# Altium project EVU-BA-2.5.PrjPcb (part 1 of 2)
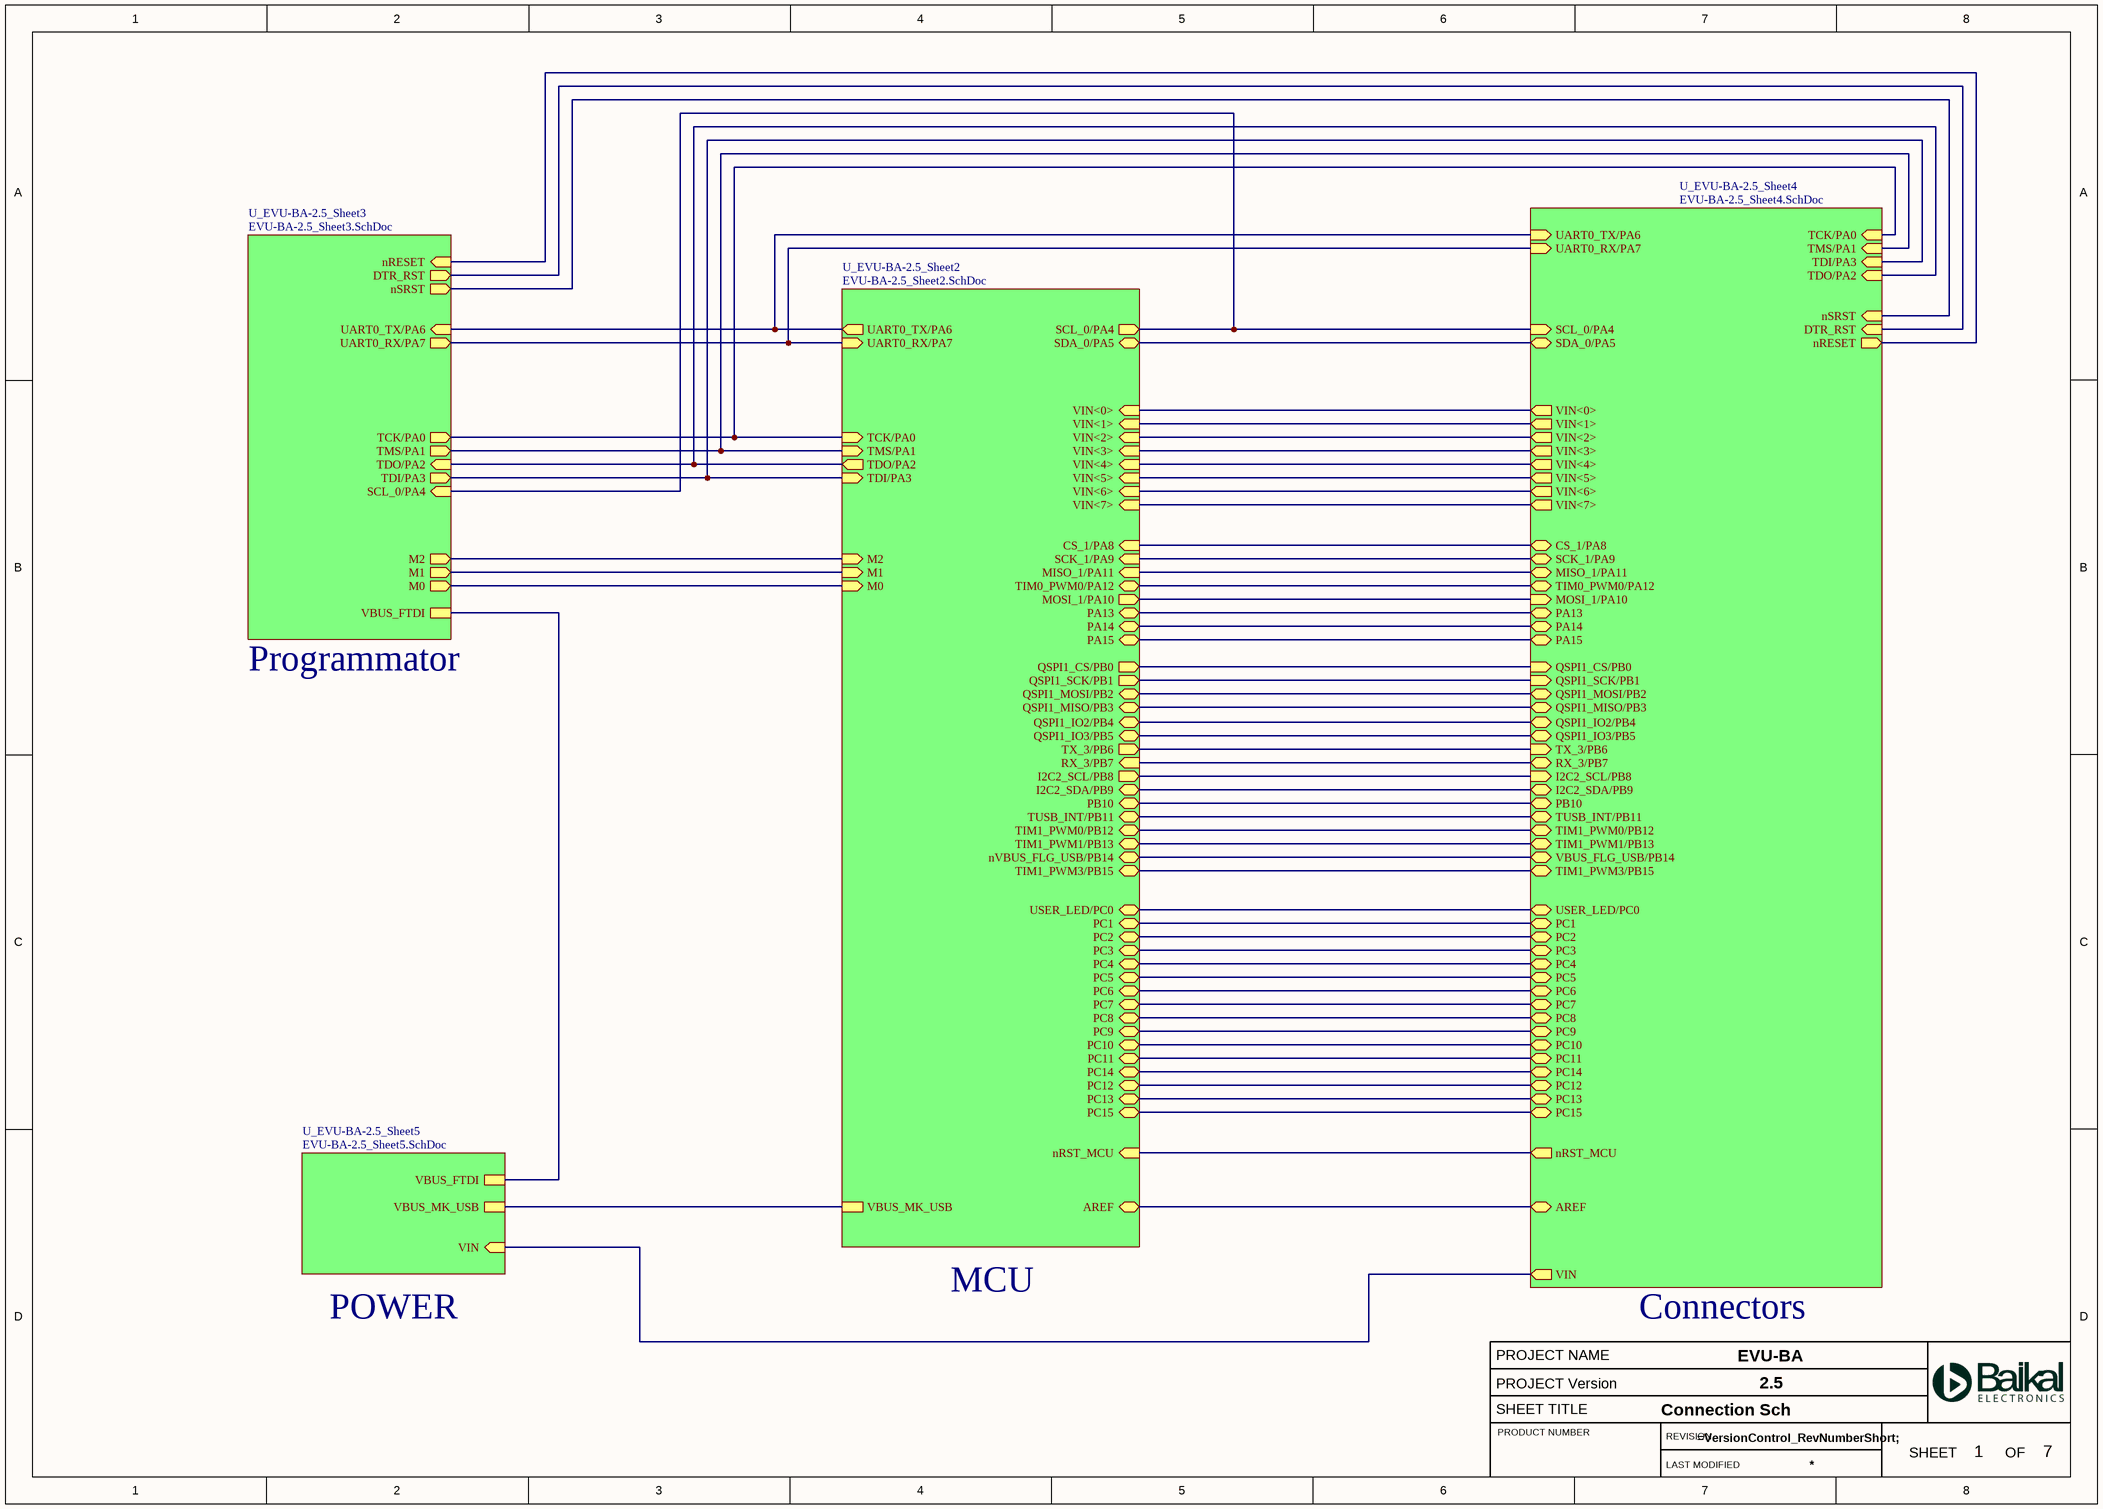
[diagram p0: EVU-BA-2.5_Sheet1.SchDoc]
Revision: =VersionControl_RevNumberShort; =CurrentTime
7 sheets, 254 parts. Net scope: hierarchical (ports join the sheet entries above them; power ports are global).
Board file: EVU-BA-2.5.PcbDoc
Sheets:
  EVU-BA-2.5_Sheet1.SchDoc
    U_EVU-BA-2.5_Sheet3 = EVU-BA-2.5_Sheet3.SchDoc
    U_EVU-BA-2.5_Sheet2 = EVU-BA-2.5_Sheet2.SchDoc
    U_EVU-BA-2.5_Sheet4 = EVU-BA-2.5_Sheet4.SchDoc
    U_EVU-BA-2.5_Sheet5 = EVU-BA-2.5_Sheet5.SchDoc
  EVU-BA-2.5_Sheet6.SchDoc
  EVU-BA-2.5_Sheet7.SchDoc

## Sheet EVU-BA-2.5_Sheet1.SchDoc: EVU-BA-2.5
size A3; ApprovedBy: Сподарец; CheckedBy: Цветков; Author: Гваськов; CompanyName: Baikal Electronics; SheetNumber: 1; SheetTotal: 7; Title2: Схема электрическая; Title3: принципиальная; PRJ: EVU-BA; Des: Baikal Electronics; VER: 2.5; TI: Connection Sch

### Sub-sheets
U_EVU-BA-2.5_Sheet2 = EVU-BA-2.5_Sheet2.SchDoc: VIN<0> (in), VIN<1> (in), VIN<2> (in), VIN<3> (in), VIN<4> (in), VIN<5> (in), VIN<6> (in), VIN<7> (in), USER_LED/PC0 (bidir), PC1 (bidir), PC2 (bidir), PC3 (bidir), PC4 (bidir), PC5 (bidir), PC6 (bidir), PC7 (bidir), PC8 (bidir), PC9 (bidir), PC10 (bidir), PC11 (bidir), PC14 (bidir), PC12 (bidir), PC13 (bidir), PC15 (bidir), TX_3/PB6 (out), RX_3/PB7 (in), TIM1_PWM0/PB12 (bidir), TIM1_PWM1/PB13 (bidir), TIM1_PWM3/PB15 (bidir), SDA_0/PA5 (bidir), TIM0_PWM0/PA12 (bidir), PA13 (bidir), PA14 (bidir), PA15 (bidir), VBUS_MK_USB, TUSB_INT/PB11 (bidir), I2C2_SDA/PB9 (bidir), PB10 (bidir), nVBUS_FLG_USB/PB14 (bidir), QSPI1_CS/PB0 (out), QSPI1_SCK/PB1 (out), QSPI1_MOSI/PB2 (bidir), QSPI1_MISO/PB3 (bidir), QSPI1_IO2/PB4 (bidir), QSPI1_IO3/PB5 (bidir), AREF (bidir), TCK/PA0 (in), TMS/PA1 (in), nRST_MCU (in), M2 (in), M1 (in), M0 (in), I2C2_SCL/PB8 (out), CS_1/PA8 (in), SCK_1/PA9 (in), MISO_1/PA11 (in), MOSI_1/PA10 (out), UART0_RX/PA7 (in), SCL_0/PA4 (out), UART0_TX/PA6 (out), TDO/PA2 (out), TDI/PA3 (in)
U_EVU-BA-2.5_Sheet3 = EVU-BA-2.5_Sheet3.SchDoc: VBUS_FTDI, SCL_0/PA4 (in), UART0_RX/PA7 (out), TCK/PA0 (out), TMS/PA1 (out), nRESET (in), nSRST (out), M2 (out), M1 (out), M0 (out), DTR_RST (out), TDI/PA3 (out), TDO/PA2 (in), UART0_TX/PA6 (in)
U_EVU-BA-2.5_Sheet4 = EVU-BA-2.5_Sheet4.SchDoc: VIN<0> (out), VIN<1> (out), VIN<2> (out), VIN<3> (out), VIN<4> (out), VIN<5> (out), VIN<6> (out), VIN<7> (out), SCL_0/PA4 (in), SDA_0/PA5 (bidir), CS_1/PA8 (bidir), SCK_1/PA9 (bidir), MISO_1/PA11 (bidir), TIM0_PWM0/PA12 (bidir), MOSI_1/PA10 (in), PA13 (bidir), PA14 (bidir), PA15 (bidir), TX_3/PB6 (in), RX_3/PB7 (bidir), TIM1_PWM0/PB12 (bidir), TIM1_PWM1/PB13 (bidir), TIM1_PWM3/PB15 (bidir), USER_LED/PC0 (bidir), PC1 (bidir), PC2 (bidir), PC3 (bidir), PC4 (bidir), PC5 (bidir), PC6 (bidir), PC7 (bidir), PC8 (bidir), PC9 (bidir), PC10 (bidir), PC11 (bidir), PC14 (bidir), PC12 (bidir), PC13 (bidir), PC15 (bidir), VIN (out), UART0_TX/PA6 (in), UART0_RX/PA7 (in), TUSB_INT/PB11 (bidir), I2C2_SCL/PB8 (in), I2C2_SDA/PB9 (bidir), PB10 (bidir), VBUS_FLG_USB/PB14 (bidir), QSPI1_CS/PB0 (in), QSPI1_SCK/PB1 (in), QSPI1_MOSI/PB2 (bidir), QSPI1_MISO/PB3 (bidir), QSPI1_IO2/PB4 (bidir), QSPI1_IO3/PB5 (bidir), AREF (bidir), TCK/PA0 (in), TMS/PA1 (in), TDI/PA3 (in), TDO/PA2 (in), nRST_MCU (out), nRESET (out), nSRST (in), DTR_RST (in)
U_EVU-BA-2.5_Sheet5 = EVU-BA-2.5_Sheet5.SchDoc: VBUS_FTDI, VIN (in), VBUS_MK_USB

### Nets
AREF: sheet U_EVU-BA-2.5_Sheet2/AREF, sheet U_EVU-BA-2.5_Sheet4/AREF
CS_1/PA8: sheet U_EVU-BA-2.5_Sheet2/CS_1/PA8, sheet U_EVU-BA-2.5_Sheet4/CS_1/PA8
DTR_RST: sheet U_EVU-BA-2.5_Sheet3/DTR_RST, sheet U_EVU-BA-2.5_Sheet4/DTR_RST
I2C2_SCL/PB8: sheet U_EVU-BA-2.5_Sheet2/I2C2_SCL/PB8, sheet U_EVU-BA-2.5_Sheet4/I2C2_SCL/PB8
I2C2_SDA/PB9: sheet U_EVU-BA-2.5_Sheet2/I2C2_SDA/PB9, sheet U_EVU-BA-2.5_Sheet4/I2C2_SDA/PB9
M0: sheet U_EVU-BA-2.5_Sheet3/M0, sheet U_EVU-BA-2.5_Sheet2/M0
M1: sheet U_EVU-BA-2.5_Sheet3/M1, sheet U_EVU-BA-2.5_Sheet2/M1
M2: sheet U_EVU-BA-2.5_Sheet3/M2, sheet U_EVU-BA-2.5_Sheet2/M2
MISO_1/PA11: sheet U_EVU-BA-2.5_Sheet2/MISO_1/PA11, sheet U_EVU-BA-2.5_Sheet4/MISO_1/PA11
MOSI_1/PA10: sheet U_EVU-BA-2.5_Sheet2/MOSI_1/PA10, sheet U_EVU-BA-2.5_Sheet4/MOSI_1/PA10
nRESET: sheet U_EVU-BA-2.5_Sheet3/nRESET, sheet U_EVU-BA-2.5_Sheet4/nRESET
nRST_MCU: sheet U_EVU-BA-2.5_Sheet2/nRST_MCU, sheet U_EVU-BA-2.5_Sheet4/nRST_MCU
nSRST: sheet U_EVU-BA-2.5_Sheet3/nSRST, sheet U_EVU-BA-2.5_Sheet4/nSRST
nVBUS_FLG_USB/PB14: sheet U_EVU-BA-2.5_Sheet2/nVBUS_FLG_USB/PB14, sheet U_EVU-BA-2.5_Sheet4/VBUS_FLG_USB/PB14
PA13: sheet U_EVU-BA-2.5_Sheet2/PA13, sheet U_EVU-BA-2.5_Sheet4/PA13
PA14: sheet U_EVU-BA-2.5_Sheet2/PA14, sheet U_EVU-BA-2.5_Sheet4/PA14
PA15: sheet U_EVU-BA-2.5_Sheet2/PA15, sheet U_EVU-BA-2.5_Sheet4/PA15
PB10: sheet U_EVU-BA-2.5_Sheet2/PB10, sheet U_EVU-BA-2.5_Sheet4/PB10
PC1: sheet U_EVU-BA-2.5_Sheet2/PC1, sheet U_EVU-BA-2.5_Sheet4/PC1
PC2: sheet U_EVU-BA-2.5_Sheet2/PC2, sheet U_EVU-BA-2.5_Sheet4/PC2
PC3: sheet U_EVU-BA-2.5_Sheet2/PC3, sheet U_EVU-BA-2.5_Sheet4/PC3
PC4: sheet U_EVU-BA-2.5_Sheet2/PC4, sheet U_EVU-BA-2.5_Sheet4/PC4
PC5: sheet U_EVU-BA-2.5_Sheet2/PC5, sheet U_EVU-BA-2.5_Sheet4/PC5
PC6: sheet U_EVU-BA-2.5_Sheet2/PC6, sheet U_EVU-BA-2.5_Sheet4/PC6
PC7: sheet U_EVU-BA-2.5_Sheet2/PC7, sheet U_EVU-BA-2.5_Sheet4/PC7
PC8: sheet U_EVU-BA-2.5_Sheet2/PC8, sheet U_EVU-BA-2.5_Sheet4/PC8
PC9: sheet U_EVU-BA-2.5_Sheet2/PC9, sheet U_EVU-BA-2.5_Sheet4/PC9
PC10: sheet U_EVU-BA-2.5_Sheet2/PC10, sheet U_EVU-BA-2.5_Sheet4/PC10
PC11: sheet U_EVU-BA-2.5_Sheet2/PC11, sheet U_EVU-BA-2.5_Sheet4/PC11
PC12: sheet U_EVU-BA-2.5_Sheet2/PC12, sheet U_EVU-BA-2.5_Sheet4/PC12
PC13: sheet U_EVU-BA-2.5_Sheet2/PC13, sheet U_EVU-BA-2.5_Sheet4/PC13
PC14: sheet U_EVU-BA-2.5_Sheet2/PC14, sheet U_EVU-BA-2.5_Sheet4/PC14
PC15: sheet U_EVU-BA-2.5_Sheet2/PC15, sheet U_EVU-BA-2.5_Sheet4/PC15
QSPI1_CS/PB0: sheet U_EVU-BA-2.5_Sheet2/QSPI1_CS/PB0, sheet U_EVU-BA-2.5_Sheet4/QSPI1_CS/PB0
QSPI1_IO2/PB4: sheet U_EVU-BA-2.5_Sheet2/QSPI1_IO2/PB4, sheet U_EVU-BA-2.5_Sheet4/QSPI1_IO2/PB4
QSPI1_IO3/PB5: sheet U_EVU-BA-2.5_Sheet2/QSPI1_IO3/PB5, sheet U_EVU-BA-2.5_Sheet4/QSPI1_IO3/PB5
QSPI1_MISO/PB3: sheet U_EVU-BA-2.5_Sheet2/QSPI1_MISO/PB3, sheet U_EVU-BA-2.5_Sheet4/QSPI1_MISO/PB3
QSPI1_MOSI/PB2: sheet U_EVU-BA-2.5_Sheet2/QSPI1_MOSI/PB2, sheet U_EVU-BA-2.5_Sheet4/QSPI1_MOSI/PB2
QSPI1_SCK/PB1: sheet U_EVU-BA-2.5_Sheet2/QSPI1_SCK/PB1, sheet U_EVU-BA-2.5_Sheet4/QSPI1_SCK/PB1
RX_3/PB7: sheet U_EVU-BA-2.5_Sheet2/RX_3/PB7, sheet U_EVU-BA-2.5_Sheet4/RX_3/PB7
SCK_1/PA9: sheet U_EVU-BA-2.5_Sheet2/SCK_1/PA9, sheet U_EVU-BA-2.5_Sheet4/SCK_1/PA9
SCL_0/PA4: sheet U_EVU-BA-2.5_Sheet3/SCL_0/PA4, sheet U_EVU-BA-2.5_Sheet2/SCL_0/PA4, sheet U_EVU-BA-2.5_Sheet4/SCL_0/PA4
SDA_0/PA5: sheet U_EVU-BA-2.5_Sheet2/SDA_0/PA5, sheet U_EVU-BA-2.5_Sheet4/SDA_0/PA5
TCK/PA0: sheet U_EVU-BA-2.5_Sheet3/TCK/PA0, sheet U_EVU-BA-2.5_Sheet2/TCK/PA0, sheet U_EVU-BA-2.5_Sheet4/TCK/PA0
TDI/PA3: sheet U_EVU-BA-2.5_Sheet3/TDI/PA3, sheet U_EVU-BA-2.5_Sheet2/TDI/PA3, sheet U_EVU-BA-2.5_Sheet4/TDI/PA3
TDO/PA2: sheet U_EVU-BA-2.5_Sheet3/TDO/PA2, sheet U_EVU-BA-2.5_Sheet2/TDO/PA2, sheet U_EVU-BA-2.5_Sheet4/TDO/PA2
TIM0_PWM0/PA12: sheet U_EVU-BA-2.5_Sheet2/TIM0_PWM0/PA12, sheet U_EVU-BA-2.5_Sheet4/TIM0_PWM0/PA12
TIM1_PWM0/PB12: sheet U_EVU-BA-2.5_Sheet2/TIM1_PWM0/PB12, sheet U_EVU-BA-2.5_Sheet4/TIM1_PWM0/PB12
TIM1_PWM1/PB13: sheet U_EVU-BA-2.5_Sheet2/TIM1_PWM1/PB13, sheet U_EVU-BA-2.5_Sheet4/TIM1_PWM1/PB13
TIM1_PWM3/PB15: sheet U_EVU-BA-2.5_Sheet2/TIM1_PWM3/PB15, sheet U_EVU-BA-2.5_Sheet4/TIM1_PWM3/PB15
TMS/PA1: sheet U_EVU-BA-2.5_Sheet3/TMS/PA1, sheet U_EVU-BA-2.5_Sheet2/TMS/PA1, sheet U_EVU-BA-2.5_Sheet4/TMS/PA1
TUSB_INT/PB11: sheet U_EVU-BA-2.5_Sheet2/TUSB_INT/PB11, sheet U_EVU-BA-2.5_Sheet4/TUSB_INT/PB11
TX_3/PB6: sheet U_EVU-BA-2.5_Sheet2/TX_3/PB6, sheet U_EVU-BA-2.5_Sheet4/TX_3/PB6
UART0_RX/PA7: sheet U_EVU-BA-2.5_Sheet3/UART0_RX/PA7, sheet U_EVU-BA-2.5_Sheet2/UART0_RX/PA7, sheet U_EVU-BA-2.5_Sheet4/UART0_RX/PA7
UART0_TX/PA6: sheet U_EVU-BA-2.5_Sheet3/UART0_TX/PA6, sheet U_EVU-BA-2.5_Sheet2/UART0_TX/PA6, sheet U_EVU-BA-2.5_Sheet4/UART0_TX/PA6
USER_LED/PC0: sheet U_EVU-BA-2.5_Sheet2/USER_LED/PC0, sheet U_EVU-BA-2.5_Sheet4/USER_LED/PC0
VBUS_FTDI: sheet U_EVU-BA-2.5_Sheet3/VBUS_FTDI, sheet U_EVU-BA-2.5_Sheet5/VBUS_FTDI
VBUS_MK_USB: sheet U_EVU-BA-2.5_Sheet2/VBUS_MK_USB, sheet U_EVU-BA-2.5_Sheet5/VBUS_MK_USB
VIN: sheet U_EVU-BA-2.5_Sheet4/VIN, sheet U_EVU-BA-2.5_Sheet5/VIN
VIN<0>: sheet U_EVU-BA-2.5_Sheet2/VIN<0>, sheet U_EVU-BA-2.5_Sheet4/VIN<0>
VIN<1>: sheet U_EVU-BA-2.5_Sheet2/VIN<1>, sheet U_EVU-BA-2.5_Sheet4/VIN<1>
VIN<2>: sheet U_EVU-BA-2.5_Sheet2/VIN<2>, sheet U_EVU-BA-2.5_Sheet4/VIN<2>
VIN<3>: sheet U_EVU-BA-2.5_Sheet2/VIN<3>, sheet U_EVU-BA-2.5_Sheet4/VIN<3>
VIN<4>: sheet U_EVU-BA-2.5_Sheet2/VIN<4>, sheet U_EVU-BA-2.5_Sheet4/VIN<4>
VIN<5>: sheet U_EVU-BA-2.5_Sheet2/VIN<5>, sheet U_EVU-BA-2.5_Sheet4/VIN<5>
VIN<6>: sheet U_EVU-BA-2.5_Sheet2/VIN<6>, sheet U_EVU-BA-2.5_Sheet4/VIN<6>
VIN<7>: sheet U_EVU-BA-2.5_Sheet2/VIN<7>, sheet U_EVU-BA-2.5_Sheet4/VIN<7>

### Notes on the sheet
- Programmator
- POWER
- MCU
- Connectors

## Sheet EVU-BA-2.5_Sheet3.SchDoc: EVU-BA-2.5
size A3; SheetNumber: 3; SheetTotal: 7; Prj: EVU-BA; Ti: USB UART Bridge; Ver: 2.5
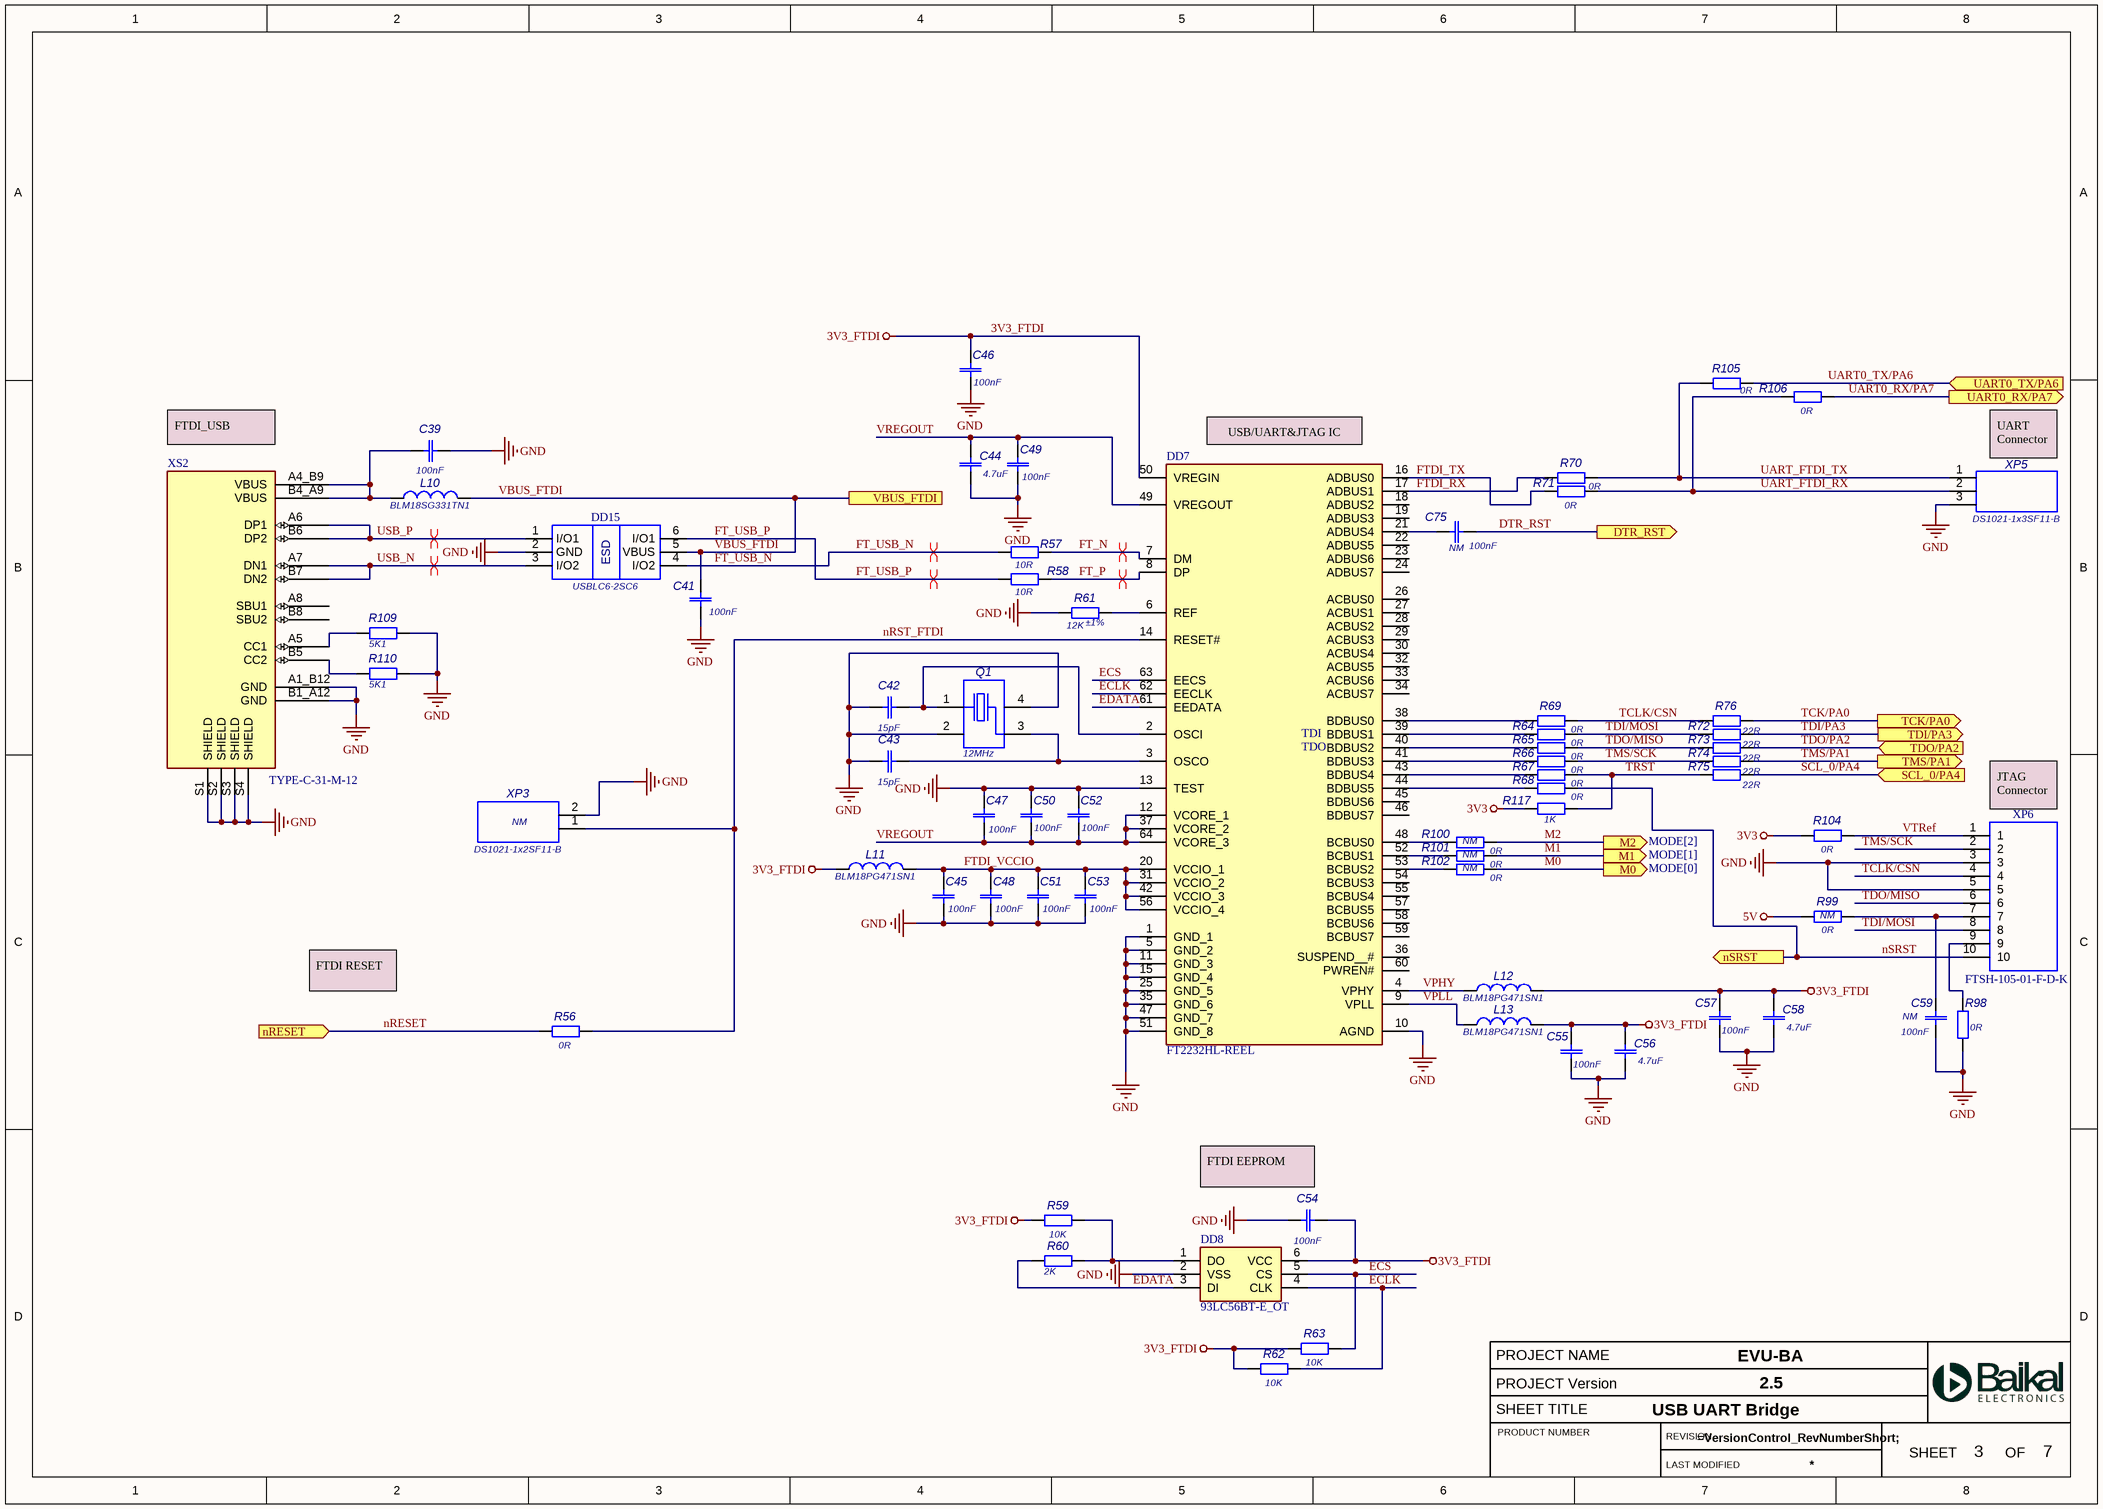
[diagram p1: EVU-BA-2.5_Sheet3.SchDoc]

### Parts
C39  value 100nF  [CAPC1608X80N]  (hidden comment: C0603C104K5RAC)
C41  value 100nF  [CAPC1608X80N]  (hidden comment: C0603C104K5RAC)
C42  value 15pF  [CAPC1005X50N]  (hidden comment: GRM1555C1H150JA01D)
C43  value 15pF  [CAPC1005X50N]  (hidden comment: GRM1555C1H150JA01D)
C44  value 4.7uF  [CAPC1608X80N]  (hidden comment: GRM188R60J475KE19D)
C45  value 100nF  [CAPC1608X80N]  (hidden comment: C0603C104K5RAC)
C46  value 100nF  [CAPC1608X80N]  (hidden comment: C0603C104K5RAC)
C47  value 100nF  [CAPC1608X80N]  (hidden comment: C0603C104K5RAC)
C48  value 100nF  [CAPC1608X80N]  (hidden comment: C0603C104K5RAC)
C49  value 100nF  [CAPC1608X80N]  (hidden comment: C0603C104K5RAC)
C50  value 100nF  [CAPC1608X80N]  (hidden comment: C0603C104K5RAC)
C51  value 100nF  [CAPC1608X80N]  (hidden comment: C0603C104K5RAC)
C52  value 100nF  [CAPC1608X80N]  (hidden comment: C0603C104K5RAC)
C53  value 100nF  [CAPC1608X80N]  (hidden comment: C0603C104K5RAC)
C54  value 100nF  [CAPC1608X80N]  (hidden comment: C0603C104K5RAC)
C55  value 100nF  [CAPC1608X80N]  (hidden comment: C0603C104K5RAC)
C56  value 4.7uF  [CAPC1608X80N]  (hidden comment: GRM188R60J475KE19D)
C57  value 100nF  [CAPC1608X80N]  (hidden comment: C0603C104K5RAC)
C58  value 4.7uF  [CAPC1608X80N]  (hidden comment: GRM188R60J475KE19D)
C59  value 100nF  DNP: NM  [CAPC1608X80N]  (hidden comment: C0603C104K5RAC)
C75  value 100nF  DNP: NM  [CAPC1608X80N]  (hidden comment: C0603C104K5RAC)
DD7  FT2232HL-REEL  [QFP50P1200X1200X160-64N]
DD8  93LC56BT-E_OT  [SOT95P280X145-6N]
DD15  USBLC6-2SC6  [SOT95P280X145-6N]
L10  BLM18SG331TN1  [INDC1608X95N]
L11  BLM18PG471SN1  [BLM18X16X08X60N]
L12  BLM18PG471SN1  [BLM18X16X08X60N]
L13  BLM18PG471SN1  [BLM18X16X08X60N]
Q1  value 12MHz  [JXS32X330X270X70N]  (hidden comment: X322512MSB4SI)
R56  value 0R  [RESC1608X45N]  (hidden comment: CR0603-J/-000-E)
R57  value 10R  [RESC1608X45N]  (hidden comment: CR0603-JW-100-E)
R58  value 10R  [RESC1608X45N]  (hidden comment: CR0603-JW-100-E)
R59  value 10K  [RESC1608X45N]  (hidden comment: CR0603-JW-103-E)
R60  value 2K  [RESC1608X45N]  (hidden comment: CR0603-JW-202-E)
R61  value 12K  Tolerance: ±1%  [RESC1608X45N]  (hidden comment: CR0603-FX-1202-E)
R62  value 10K  [RESC1608X45N]  (hidden comment: CR0603-JW-103-E)
R63  value 10K  [RESC1608X45N]  (hidden comment: CR0603-JW-103-E)
R64  value 0R  [RESC1608X45N]  (hidden comment: CR0603-J/-000-E)
R65  value 0R  [RESC1608X45N]  (hidden comment: CR0603-J/-000-E)
R66  value 0R  [RESC1608X45N]  (hidden comment: CR0603-J/-000-E)
R67  value 0R  [RESC1608X45N]  (hidden comment: CR0603-J/-000-E)
R68  value 0R  [RESC1608X45N]  (hidden comment: CR0603-J/-000-E)
R69  value 0R  [RESC1608X45N]  (hidden comment: CR0603-J/-000-E)
R70  value 0R  [RESC1608X45N]  (hidden comment: CR0603-J/-000-E)
R71  value 0R  [RESC1608X45N]  (hidden comment: CR0603-J/-000-E)
R72  value 22R  [RESC1608X45N]  (hidden comment: CR0603-JW-220-E)
R73  value 22R  [RESC1608X45N]  (hidden comment: CR0603-JW-220-E)
R74  value 22R  [RESC1608X45N]  (hidden comment: CR0603-JW-220-E)
R75  value 22R  [RESC1608X45N]  (hidden comment: CR0603-JW-220-E)
R76  value 22R  [RESC1608X45N]  (hidden comment: CR0603-JW-220-E)
R98  value 0R  [RESC1608X45N]  (hidden comment: CR0603-J/-000-E)
R99  value 0R  DNP: NM  [RESC1608X45N]  (hidden comment: CR0603-J/-000-E)
R100  value 0R  DNP: NM  [RESC1608X45N]  (hidden comment: CR0603-J/-000-E)
R101  value 0R  DNP: NM  [RESC1608X45N]  (hidden comment: CR0603-J/-000-E)
R102  value 0R  DNP: NM  [RESC1608X45N]  (hidden comment: CR0603-J/-000-E)
R104  value 0R  [RESC1608X45N]  (hidden comment: CR0603-J/-000-E)
R105  value 0R  [RESC1608X45N]  (hidden comment: CR0603-J/-000-E)
R106  value 0R  [RESC1608X45N]  (hidden comment: CR0603-J/-000-E)
R109  Value Eng: 5K1  [RESC1608X45N]  (hidden comment: CR0603-JW-512-E)
R110  Value Eng: 5K1  [RESC1608X45N]  (hidden comment: CR0603-JW-512-E)
R117  Value Eng: 1K  [RESC1608X45N]  (hidden comment: CR0603-JW-102-E)
XP3  DS1021-1x2SF11-B  DNP: NM  [PLS2-254PX50X25X854N]
XP5  DS1021-1x3SF11-B  [PLS3-254PX76X25X854N]
XP6  FTSH-105-01-F-D-K  [FTSH-105-XX-YYY-D-K]
XS2  TYPE-C-31-M-12  [TYPE-C-31-M-12]

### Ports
DTR_RST (out, see EVU-BA-2.5_Sheet1[7D], EVU-BA-2.5_Sheet4[6A]), M0 (out, see EVU-BA-2.5_Sheet1[7C], EVU-BA-2.5_Sheet2[8D]), M1 (out, see EVU-BA-2.5_Sheet1[7C], EVU-BA-2.5_Sheet2[8D]), M2 (out, see EVU-BA-2.5_Sheet1[7C], EVU-BA-2.5_Sheet2[8D]), nRESET (in, see EVU-BA-2.5_Sheet1[7D], EVU-BA-2.5_Sheet4[7A]), nSRST (out, see EVU-BA-2.5_Sheet1[7D], EVU-BA-2.5_Sheet4[7A]), SCL_0/PA4 (in, see EVU-BA-2.5_Sheet1[7C], EVU-BA-2.5_Sheet2[5D], EVU-BA-2.5_Sheet4[8D]), TCK/PA0 (out, see EVU-BA-2.5_Sheet1[7C], EVU-BA-2.5_Sheet2[5D], EVU-BA-2.5_Sheet4[8D]), TDI/PA3 (out, see EVU-BA-2.5_Sheet1[7C], EVU-BA-2.5_Sheet2[5D], EVU-BA-2.5_Sheet4[8D]), TDO/PA2 (in, see EVU-BA-2.5_Sheet1[7C], EVU-BA-2.5_Sheet2[5D], EVU-BA-2.5_Sheet4[8D]), TMS/PA1 (out, see EVU-BA-2.5_Sheet1[7C], EVU-BA-2.5_Sheet2[5D], EVU-BA-2.5_Sheet4[8D]), UART0_RX/PA7 (out, see EVU-BA-2.5_Sheet1[7D], EVU-BA-2.5_Sheet2[5D], EVU-BA-2.5_Sheet4[8D]), UART0_TX/PA6 (in, see EVU-BA-2.5_Sheet1[7D], EVU-BA-2.5_Sheet2[5D], EVU-BA-2.5_Sheet4[8D]), VBUS_FTDI (see EVU-BA-2.5_Sheet1[7C], EVU-BA-2.5_Sheet5[8D])

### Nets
3V3: R104.1 R117.1
3V3_FTDI: C46.2 C54.1 C55.2 C56.2 C57.2 C58.2 DD7.50(VREGIN) DD8.6(VCC) L11.1 L12.2 L13.2 R59.1 R62.1 R63.1
5V: R99.2
GND: C39.2 C41.2 C42.1 C43.1 C44.1 C45.1 C46.1 C47.2 C48.1 C49.1 C50.2 C51.1 C52.2 C53.1 C54.2 C55.1 C56.1 C57.1 C58.1 C59.1 DD7.1(GND_1) DD7.5(GND_2) DD7.10(AGND) DD7.11(GND_3) DD7.13(TEST) DD7.15(GND_4) DD7.25(GND_5) DD7.35(GND_6) DD7.47(GND_7) DD7.51(GND_8) DD8.2(VSS) DD15.2(GND) Q1.2 Q1.4 R61.1 R98.2 R109.2 R110.2 XP3.2 XP5.3 XP6.3 XP6.5 XS2.A1_B12(GND) XS2.B1_A12(GND) XS2.S1(SHIELD) XS2.S2(SHIELD) XS2.S3(SHIELD) XS2.S4(SHIELD)
DTR_RST: C75.1 ; port DTR_RST
ECLK: DD7.62(EECLK) DD8.4(CLK) R62.2
ECS: DD7.63(EECS) DD8.5(CS) R63.2
EDATA: DD7.61(EEDATA) DD8.3(DI) R60.1
FT_N: DD7.7(DM) R57.2
FT_P: DD7.8(DP) R58.2
FT_USB_N: DD15.4(I/O2) R57.1
FT_USB_P: DD15.6(I/O1) R58.1
FTDI_RX: DD7.17(ADBUS1) R70.1
FTDI_TX: DD7.16(ADBUS0) R71.1
FTDI_VCCIO: C45.2 C48.2 C51.2 C53.2 DD7.20(VCCIO_1) DD7.31(VCCIO_2) DD7.42(VCCIO_3) DD7.56(VCCIO_4) L11.2
M0: R102.2 ; port M0
M1: R101.2 ; port M1
M2: R100.2 ; port M2
nRESET: R56.1 ; port nRESET
nRST_FTDI: DD7.14(RESET#) R56.2 XP3.1
nSRST: R68.2 XP6.10 ; port nSRST
SCL_0/PA4: R75.2 ; port SCL_0/PA4
TCK/PA0: R76.2 ; port TCK/PA0
TCLK/CSN: R69.2 R76.1 XP6.4
TDI/MOSI: R64.2 R72.1 XP6.8
TDI/PA3: R72.2 ; port TDI/PA3
TDO/MISO: R65.2 R73.1 XP6.6
TDO/PA2: R73.2 ; port TDO/PA2
TMS/PA1: R74.2 ; port TMS/PA1
TMS/SCK: R66.2 R74.1 XP6.2
TRST: R67.2 R75.1 R117.2
UART0_RX/PA7: R106.2 ; port UART0_RX/PA7
UART0_TX/PA6: R105.2 ; port UART0_TX/PA6
UART_FTDI_RX: R71.2 R106.1 XP5.2
UART_FTDI_TX: R70.2 R105.1 XP5.1
USB_N: DD15.3(I/O2) XS2.A7(DN1) XS2.B7(DN2)
USB_P: DD15.1(I/O1) XS2.A6(DP1) XS2.B6(DP2)
VBUS_FTDI: C41.1 DD15.5(VBUS) L10.2 ; port VBUS_FTDI
VPHY: DD7.4(VPHY) L12.1
VPLL: DD7.9(VPLL) L13.1
VREGOUT: C44.2 C47.1 C49.2 C50.1 C52.1 DD7.12(VCORE_1) DD7.37(VCORE_2) DD7.49(VREGOUT) DD7.64(VCORE_3)
VTRef: R104.2 XP6.1
NetC39_1: C39.1 L10.1 XS2.A4_B9(VBUS) XS2.B4_A9(VBUS)
NetC42_2: C42.2 DD7.2(OSCI) Q1.1
NetC43_2: C43.2 DD7.3(OSCO) Q1.3
NetC59_2: C59.2 R99.1 XP6.7
NetC75_2: C75.2 DD7.21(ADBUS4)
NetDD7_6: DD7.6(REF) R61.2
NetDD7_38: DD7.38(BDBUS0) R69.1
NetDD7_39: DD7.39(BDBUS1) R64.1
NetDD7_40: DD7.40(BDBUS2) R65.1
NetDD7_41: DD7.41(BDBUS3) R66.1
NetDD7_43: DD7.43(BDBUS4) R67.1
NetDD7_44: DD7.44(BDBUS5) R68.1
NetDD7_48: DD7.48(BCBUS0) R100.1
NetDD7_52: DD7.52(BCBUS1) R101.1
NetDD7_53: DD7.53(BCBUS2) R102.1
NetDD8_1: DD8.1(DO) R59.2 R60.2
NetR98_1: R98.1 XP6.9
NetR109_1: R109.1 XS2.A5(CC1)
NetR110_1: R110.1 XS2.B5(CC2)

Not connected (* = marked no-connect by the designer): DD7 18(ADBUS2) 19(ADBUS3) 22(ADBUS5) 23(ADBUS6) 24(ADBUS7) 26(ACBUS0) 27(ACBUS1) 28(ACBUS2) 29(ACBUS3) 30(ACBUS4) 32(ACBUS5) 33(ACBUS6) 34(ACBUS7) 36(SUSPEND__#) 45(BDBUS6) 46(BDBUS7) 54(BCBUS3) 55(BCBUS4) 57(BCBUS5) 58(BCBUS6) 59(BCBUS7) 60(PWREN#); XS2 A8(SBU1) B8(SBU2)

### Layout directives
differential pair: FT_N, FT_P, FT_USB_N, FT_USB_P, USB_N, USB_P

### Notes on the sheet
- (near XS2) FTDI_USB
- (near DD7) USB/UART&JTAG IC
- (near XP5) UART Connector
- (near DD7) TDI
- (near DD7) TDO
- MODE[1]
- MODE[2]
- (near XP6) JTAG Connector
- MODE[0]
- FTDI RESET
- (near C54) FTDI EEPROM

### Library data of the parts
C39 C41 C45-C55 C57 C59 C75 = C0603C104K5RAC: 0603 X7R 0,1 uF ±10% 50V; Manufacturer: "Kemet"; NOM: 0603 X7R 100nF ±10% 50V; Value Ru: 0,1 мкФ
C42 C43 = GRM1555C1H150JA01D: 0402 COG 15 pF±5% 50V; Manufacturer: "Murata"; Tolerance: ±5%; Value Ru: 15 пФ
C44 C56 C58 = GRM188R60J475KE19D: 0603 X5R 4,7 uF ±10% 6,3V; Manufacturer: "Murata"; Power_Voltage: 6,3V; NOM: 0603 X5R 4.7uF ±10% 6,3V; Value Ru: 4.7 мкФ
DD7 = FT2232HL-REEL: USB-UART/FIFO; Manufacturer: "FTDI Chip"; TKE: LQFP-64
DD8 = 93LC56BT-E_OT: EEPROM, 2KBIT, SERIAL, 2MHz; Manufacturer_Part_Number: 93LC56BT-E/OT; Manufacturer: "Microchip"; TKE: SOT-23-6
DD15 = USBLC6-2SC6: Very low capacitance ESD protector; Manufacturer: "STMicroelectronics"; MARK: UL26
L10 = BLM18SG331TN1: 330 Ohms/100 MHz 1,5A 0,07 Ohms; Manufacturer: "Murata"; Value Ru: 330 Ом/100MГц 1,5А 0,07 Ом
L11-L13 = BLM18PG471SN1: 470 Ohms/100MHz 1A 0,2 Ohms; Manufacturer: "Murata"; Value Ru: 470 Ом/100MГц 1А 0,2 Ом
Q1 = X322512MSB4SI: Quartz Crystal 12MHz; Manufacturer: "YXC"; MARK: YXC 12.0 XXXX; Value Ru: 12,000 МГц
R56 R64-R71 R98-R102 R104-R106 = CR0603-J/-000-E: 0603 0 Ohm 0,1W; Manufacturer: "Bourns"; TKE: 0603; MARK: 000; NOM: 0603 0R; Value Ru: 0 Ом; Replacement: RC0603JR-070RL
R57 R58 = CR0603-JW-100-E: 0603 10 Ohm±5% 0.1W; Manufacturer: "Bourns"; TKE: 0603; MARK: 100; Power_Voltage: 0,1W; NOM: 0603 10R ±5% 0,1W; Tolerance: ±5%; Value Ru: 10 Ом
R59 R62 R63 = CR0603-JW-103-E: 0603 10 kOhm±5% 0,1W; Manufacturer: "Bourns"; TKE: 0603; MARK: 103; Power_Voltage: 0,1W; NOM: 0603 10K ±5% 0,1W; Tolerance: ±5%; Value Ru: 10 кОм
R60 = CR0603-JW-202-E: 0603 2 kOhm±5% 0.1W; Manufacturer: "Bourns"; TKE: 0603; MARK: 202; Power_Voltage: 0,1 Вт; NOM: 0603 2K ±5% 0,1 Вт; Tolerance: ±5%; Value Ru: 2 кОм
R61 = CR0603-FX-1202-E: 0603 12 kOhm±1% 0,1W; ManufacturerPartNumber: CR0603-JW-123-E; Manufacturer: "Bourns"; TKE: 0603; MARK: 123; Power_Voltage: 0,1 Вт; NOM: 0603 12K ±1% 0,1 Вт; Value Ru: 12 кОм
R72-R76 = CR0603-JW-220-E: 0603 22 Ohm ±5% 0.1W; Manufacturer: "Bourns"; TKE: 0603; MARK: 220; NOM: 0603 22R ±5% 0,1 Вт; Power_Voltage: 0,1 Вт; Value Ru: 22 Ом
R109 R110 = CR0603-JW-512-E: 0603 5,1 kOhm±5% 0,1W; ManufacturerPartNumber: CR0603-JW-682-E; Manufacturer: "Bourns"; TKE: 0603; MARK: 512; Power_Voltage: 0,1 Вт; NOM: 0603 5,1 кОм ±5% 0,1 Вт; Tolerance: ±5%; Value: 5,1 кОм
R117 = CR0603-JW-102-E: 0603 1 kOhm±5% 0,1W; Manufacturer: "Bourns"; TKE: 0603; MARK: 102; Power_Voltage: 0,1 Вт; NOM: 0603 1 кОм ±5% 0,1 Вт; Tolerance: ±5%; Value: 1 кОм
XP3 = DS1021-1x2SF11-B: Connector 2.54 pitch, 1 row, 8.54 height, 2 pins per row; Manufacturer: "Connfly"
XP5 = DS1021-1x3SF11-B: Connector 2.54 pitch, 1 row, 8.54 height, 3 pins per row; Manufacturer: "Connfly"
XP6 = FTSH-105-01-F-D-K: Connector 1.27 pitch, 2 rows, 5 pins per row; Manufacturer_Name: SAMTEC; Manufacturer: "Samtec"
XS2 = TYPE-C-31-M-12: USB TYPE-C 5A 16P Female SMD USB Connectors; Manufacturer: "HRO"; MF: Hro Electronics (Beijing) Co

## Sheet EVU-BA-2.5_Sheet2.SchDoc: EVU-BA-2.5
size A3; SheetNumber: 2; SheetTotal: 7; Prj: EVU-BA; Ver: 2.5; Ti: Microcontroller
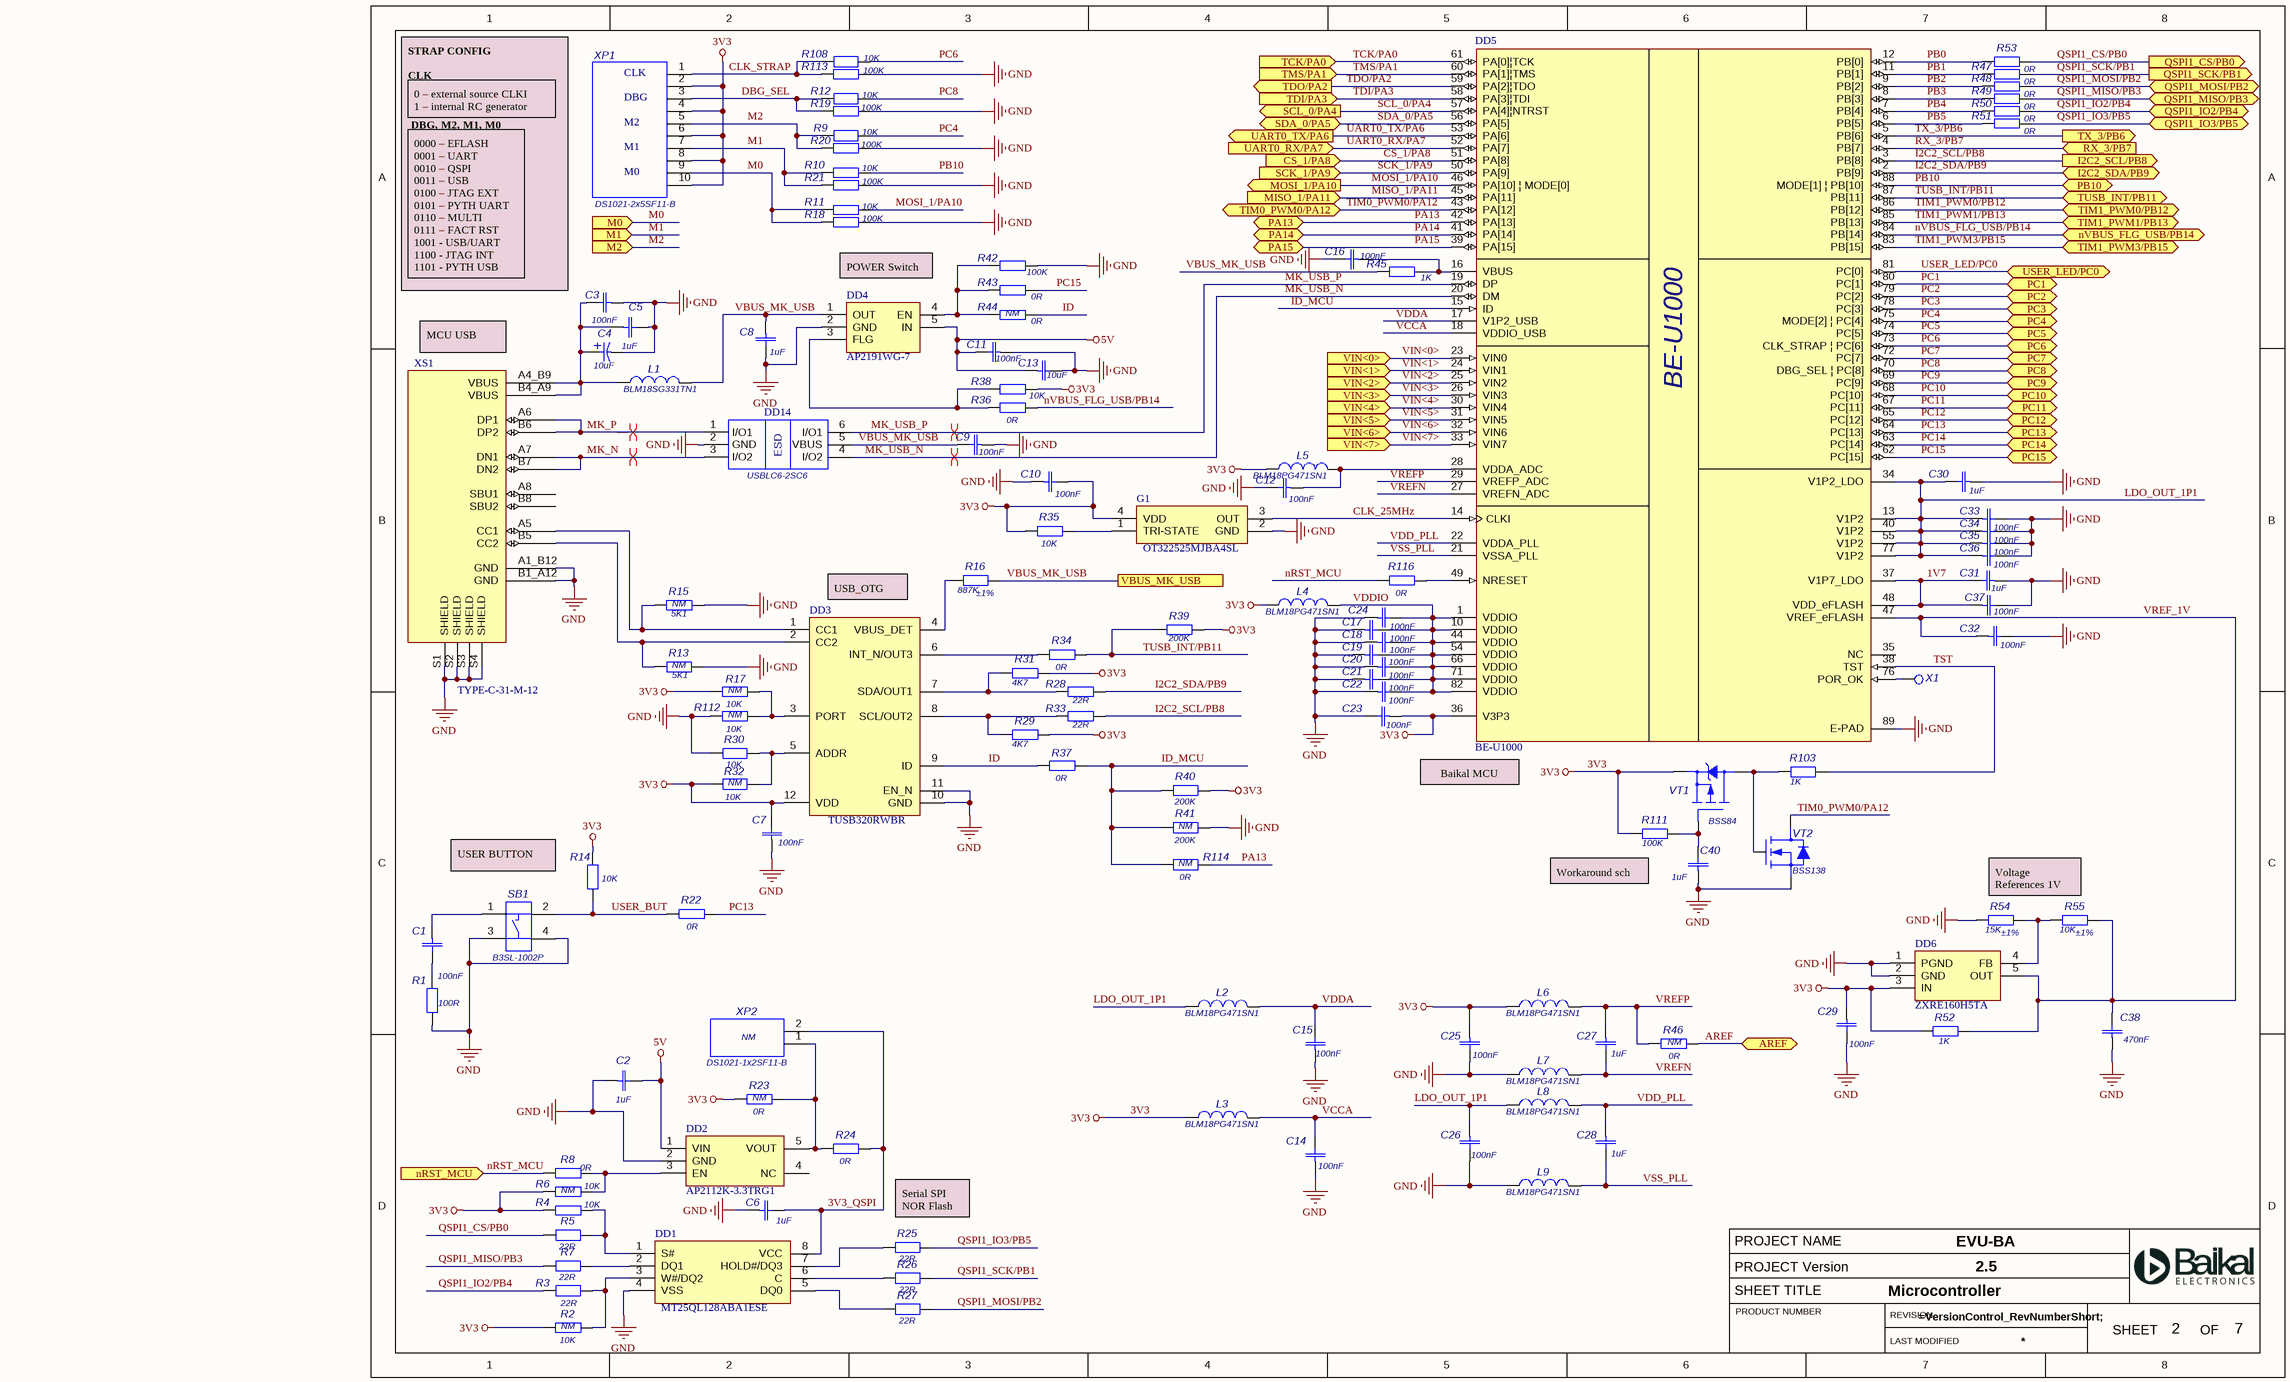
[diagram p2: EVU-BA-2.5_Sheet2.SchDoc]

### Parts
C1  value 100nF  [CAPC1608X80N]  (hidden comment: C0603C104K5RAC)
C2  value 1uF  [CAPC1608X80N]  (hidden comment: GRM188R71C105KA12D)
C3  value 100nF  [CAPC1608X80N]  (hidden comment: C0603C104K5RAC)
C4  value 10uF  [CAPPM3528X210N]  (hidden comment: 293D106X0020B2TE3)
C5  value 1uF  [CAPC1608X80N]  (hidden comment: GRM188R71C105KA12D)
C6  value 1uF  [CAPC1608X80N]  (hidden comment: GRM188R71C105KA12D)
C7  value 100nF  [CAPC1608X80N]  (hidden comment: C0603C104K5RAC)
C8  value 1uF  [CAPC1608X80N]  (hidden comment: GRM188R71C105KA12D)
C9  value 100nF  [CAPC1608X80N]  (hidden comment: C0603C104K5RAC)
C10  value 100nF  [CAPC1608X80N]  (hidden comment: C0603C104K5RAC)
C11  value 100nF  [CAPC1608X80N]  (hidden comment: C0603C104K5RAC)
C12  value 100nF  [CAPC1608X80N]  (hidden comment: C0603C104K5RAC)
C13  value 10uF  [CAPC3216X160N]  (hidden comment: GRM31CR71E106KA12L)
C14  value 100nF  [CAPC1608X80N]  (hidden comment: C0603C104K5RAC)
C15  value 100nF  [CAPC1608X80N]  (hidden comment: C0603C104K5RAC)
C16  value 100nF  [CAPC1608X80N]  (hidden comment: C0603C104K5RAC)
C17  value 100nF  [CAPC1608X80N]  (hidden comment: C0603C104K5RAC)
C18  value 100nF  [CAPC1608X80N]  (hidden comment: C0603C104K5RAC)
C19  value 100nF  [CAPC1608X80N]  (hidden comment: C0603C104K5RAC)
C20  value 100nF  [CAPC1608X80N]  (hidden comment: C0603C104K5RAC)
C21  value 100nF  [CAPC1608X80N]  (hidden comment: C0603C104K5RAC)
C22  value 100nF  [CAPC1608X80N]  (hidden comment: C0603C104K5RAC)
C23  value 100nF  [CAPC1608X80N]  (hidden comment: C0603C104K5RAC)
C24  value 100nF  [CAPC1608X80N]  (hidden comment: C0603C104K5RAC)
C25  value 100nF  [CAPC1608X80N]  (hidden comment: C0603C104K5RAC)
C26  value 100nF  [CAPC1608X80N]  (hidden comment: C0603C104K5RAC)
C27  value 1uF  [CAPC1608X80N]  (hidden comment: GRM188R71C105KA12D)
C28  value 1uF  [CAPC1608X80N]  (hidden comment: GRM188R71C105KA12D)
C29  value 100nF  [CAPC1608X80N]  (hidden comment: C0603C104K5RAC)
C30  value 1uF  [CAPC1608X80N]  (hidden comment: GRM188R71C105KA12D)
C31  value 1uF  [CAPC1608X80N]  (hidden comment: GRM188R71C105KA12D)
C32  value 100nF  [CAPC1608X80N]  (hidden comment: C0603C104K5RAC)
C33  value 100nF  [CAPC1608X80N]  (hidden comment: C0603C104K5RAC)
C34  value 100nF  [CAPC1608X80N]  (hidden comment: C0603C104K5RAC)
C35  value 100nF  [CAPC1608X80N]  (hidden comment: C0603C104K5RAC)
C36  value 100nF  [CAPC1608X80N]  (hidden comment: C0603C104K5RAC)
C37  value 100nF  [CAPC1608X80N]  (hidden comment: C0603C104K5RAC)
C38  value 470nF  [CAPC1608X80N]  (hidden comment: GRM188R71E474KA12D)
C40  value 1uF  [CAPC1608X80N]  (hidden comment: GRM188R71C105KA12D)
DD1  MT25QL128ABA1ESE  [SOIC127P790X216-8N]
DD2  AP2112K-3.3TRG1  [SOT95P285X140-5N]
DD3  TUSB320RWBR  [TUSB320RWBR]
DD4  AP2191WG-7  [SOT95P285X140-5N]
DD5  BE-U1000  [QFNWB10X10-88L-AL]
DD6  ZXRE160H5TA  [SOT65P210X110-5N]
DD14  USBLC6-2SC6  [SOT95P280X145-6N]
G1  OT322525MJBA4SL  [OT322525MJBA4SL]
L1  BLM18SG331TN1  [INDC1608X95N]
L2  BLM18PG471SN1  [BLM18X16X08X60N]
L3  BLM18PG471SN1  [BLM18X16X08X60N]
L4  BLM18PG471SN1  [BLM18X16X08X60N]
L5  BLM18PG471SN1  [BLM18X16X08X60N]
L6  BLM18PG471SN1  [BLM18X16X08X60N]
L7  BLM18PG471SN1  [BLM18X16X08X60N]
L8  BLM18PG471SN1  [BLM18X16X08X60N]
L9  BLM18PG471SN1  [BLM18X16X08X60N]
R1  value 100R  [RESC1608X45N]  (hidden comment: CR0603-JW-101-E)
R2  value 10K  DNP: NM  [RESC1608X45N]  (hidden comment: CR0603-JW-103-E)
R3  value 22R  [RESC1608X45N]  (hidden comment: CR0603-JW-220-E)
R4  value 10K  [RESC1608X45N]  (hidden comment: CR0603-JW-103-E)
R5  value 22R  [RESC1608X45N]  (hidden comment: CR0603-JW-220-E)
R6  value 10K  DNP: NM  [RESC1608X45N]  (hidden comment: CR0603-JW-103-E)
R7  value 22R  [RESC1608X45N]  (hidden comment: CR0603-JW-220-E)
R8  value 0R  [RESC1608X45N]  (hidden comment: CR0603-J/-000-E)
R9  value 10K  [RESC1608X45N]  (hidden comment: CR0603-JW-103-E)
R10  value 10K  [RESC1608X45N]  (hidden comment: CR0603-JW-103-E)
R11  value 10K  [RESC1608X45N]  (hidden comment: CR0603-JW-103-E)
R12  value 10K  [RESC1608X45N]  (hidden comment: CR0603-JW-103-E)
R13  Value Eng: 5K1  DNP: NM  [RESC1608X45N]  (hidden comment: CR0603-JW-512-E)
R14  value 10K  [RESC1608X45N]  (hidden comment: CR0603-JW-103-E)
R15  Value Eng: 5K1  DNP: NM  [RESC1608X45N]  (hidden comment: CR0603-JW-512-E)
R16  value 887K  Tolerance: ±1%  [RESC1608X45N]  (hidden comment: CR0603-FX-8873-E)
R17  value 10K  DNP: NM  [RESC1608X45N]  (hidden comment: CR0603-JW-103-E)
R18  value 100K  [RESC1608X45N]  (hidden comment: CR0603-JW-104-E)
R19  value 100K  [RESC1608X45N]  (hidden comment: CR0603-JW-104-E)
R20  value 100K  [RESC1608X45N]  (hidden comment: CR0603-JW-104-E)
R21  value 100K  [RESC1608X45N]  (hidden comment: CR0603-JW-104-E)
R22  value 0R  [RESC1608X45N]  (hidden comment: CR0603-J/-000-E)
R23  value 0R  DNP: NM  [RESC1608X45N]  (hidden comment: CR0603-J/-000-E)
R24  value 0R  [RESC1608X45N]  (hidden comment: CR0603-J/-000-E)
R25  value 22R  [RESC1608X45N]  (hidden comment: CR0603-JW-220-E)
R26  value 22R  [RESC1608X45N]  (hidden comment: CR0603-JW-220-E)
R27  value 22R  [RESC1608X45N]  (hidden comment: CR0603-JW-220-E)
R28  value 22R  [RESC1608X45N]  (hidden comment: CR0603-JW-220-E)
R29  value 4K7  [RESC1608X45N]  (hidden comment: CR0603-JW-472-E)
R30  value 10K  [RESC1608X45N]  (hidden comment: CR0603-JW-103-E)
R31  value 4K7  [RESC1608X45N]  (hidden comment: CR0603-JW-472-E)
R32  value 10K  DNP: NM  [RESC1608X45N]  (hidden comment: CR0603-JW-103-E)
R33  value 22R  [RESC1608X45N]  (hidden comment: CR0603-JW-220-E)
R34  value 0R  [RESC1608X45N]  (hidden comment: CR0603-J/-000-E)
R35  value 10K  [RESC1608X45N]  (hidden comment: CR0603-JW-103-E)
R36  value 0R  [RESC1608X45N]  (hidden comment: CR0603-J/-000-E)
R37  value 0R  [RESC1608X45N]  (hidden comment: CR0603-J/-000-E)
R38  value 10K  [RESC1608X45N]  (hidden comment: CR0603-JW-103-E)
R39  value 200K  [RESC1608X45N]  (hidden comment: CR0603-JW-204-E)
R40  value 200K  [RESC1608X45N]  (hidden comment: CR0603-JW-204-E)
R41  value 200K  DNP: NM  [RESC1608X45N]  (hidden comment: CR0603-JW-204-E)
R42  value 100K  [RESC1608X45N]  (hidden comment: CR0603-JW-104-E)
R43  value 0R  [RESC1608X45N]  (hidden comment: CR0603-J/-000-E)
R44  value 0R  DNP: NM  [RESC1608X45N]  (hidden comment: CR0603-J/-000-E)
R45  Value Eng: 1K  [RESC1608X45N]  (hidden comment: CR0603-JW-102-E)
R46  value 0R  DNP: NM  [RESC1608X45N]  (hidden comment: CR0603-J/-000-E)
R47  value 0R  [RESC1608X45N]  (hidden comment: CR0603-J/-000-E)
R48  value 0R  [RESC1608X45N]  (hidden comment: CR0603-J/-000-E)
R49  value 0R  [RESC1608X45N]  (hidden comment: CR0603-J/-000-E)
R50  value 0R  [RESC1608X45N]  (hidden comment: CR0603-J/-000-E)
R51  value 0R  [RESC1608X45N]  (hidden comment: CR0603-J/-000-E)
R52  Value Eng: 1K  [RESC1608X45N]  (hidden comment: CR0603-JW-102-E)
R53  value 0R  [RESC1608X45N]  (hidden comment: CR0603-J/-000-E)
R54  value 15K  Tolerance: ±1%  [RESC1608X45N]  (hidden comment: CR0603-FX-1502-E)
R55  value 10K  Tolerance: ±1%  [RESC1608X45N]  (hidden comment: CR0603-FX-1002-E)
R103  Value Eng: 1K  [RESC1608X45N]  (hidden comment: CR0603-JW-102-E)
R108  value 10K  [RESC1608X45N]  (hidden comment: CR0603-JW-103-E)
R111  value 100K  [RESC1608X45N]  (hidden comment: CR0603-JW-104-E)
R112  value 10K  DNP: NM  [RESC1608X45N]  (hidden comment: CR0603-JW-103-E)
R113  value 100K  [RESC1608X45N]  (hidden comment: CR0603-JW-104-E)
R114  value 0R  DNP: NM  [RESC1608X45N]  (hidden comment: CR0603-J/-000-E)
R116  value 0R  [RESC1608X45N]  (hidden comment: CR0603-J/-000-E)
SB1  B3SL-1002P  [B3SL-1002P]
VT1  BSS84  [SOT95P230X110-3N]
VT2  BSS138  [SOT95P230X110-3N]
X1  PAD_SMD25X25  [PAD_SMD25X25]  (value not drawn)  (no BOM)
XP1  DS1021-2x5SF11-B  [PLD10-254PX1278X254X854N]
XP2  DS1021-1x2SF11-B  DNP: NM  [PLS2-254PX50X25X854N]
XS1  TYPE-C-31-M-12  [TYPE-C-31-M-12]

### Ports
AREF (bidir, see EVU-BA-2.5_Sheet1[4A], EVU-BA-2.5_Sheet4[8B]), CS_1/PA8 (in, see EVU-BA-2.5_Sheet1[4C], EVU-BA-2.5_Sheet4[8D]), I2C2_SCL/PB8 (out, see EVU-BA-2.5_Sheet1[4B], EVU-BA-2.5_Sheet4[8C]), I2C2_SDA/PB9 (bidir, see EVU-BA-2.5_Sheet1[4B], EVU-BA-2.5_Sheet4[8C]), M0 (in, see EVU-BA-2.5_Sheet1[5C], EVU-BA-2.5_Sheet3[2B]), M1 (in, see EVU-BA-2.5_Sheet1[5C], EVU-BA-2.5_Sheet3[2B]), M2 (in, see EVU-BA-2.5_Sheet1[5C], EVU-BA-2.5_Sheet3[2B]), MISO_1/PA11 (in, see EVU-BA-2.5_Sheet1[4C], EVU-BA-2.5_Sheet4[8D]), MOSI_1/PA10 (out, see EVU-BA-2.5_Sheet1[4C], EVU-BA-2.5_Sheet4[8D]), nRST_MCU (in, see EVU-BA-2.5_Sheet1[4A], EVU-BA-2.5_Sheet4[4A]), nVBUS_FLG_USB/PB14 (bidir, see EVU-BA-2.5_Sheet1[4B]), PA13 (bidir, see EVU-BA-2.5_Sheet1[4C], EVU-BA-2.5_Sheet4[8D]), PA14 (bidir, see EVU-BA-2.5_Sheet1[4C], EVU-BA-2.5_Sheet4[8C]), PA15 (bidir, see EVU-BA-2.5_Sheet1[4C], EVU-BA-2.5_Sheet4[8C]), PB10 (bidir, see EVU-BA-2.5_Sheet1[4B], EVU-BA-2.5_Sheet4[8C]), PC1 (bidir, see EVU-BA-2.5_Sheet1[4B], EVU-BA-2.5_Sheet4[8C]), PC2 (bidir, see EVU-BA-2.5_Sheet1[4B], EVU-BA-2.5_Sheet4[8C]), PC3 (bidir, see EVU-BA-2.5_Sheet1[4B], EVU-BA-2.5_Sheet4[8C]), PC4 (bidir, see EVU-BA-2.5_Sheet1[4B], EVU-BA-2.5_Sheet4[8C]), PC5 (bidir, see EVU-BA-2.5_Sheet1[4B], EVU-BA-2.5_Sheet4[8C]), PC6 (bidir, see EVU-BA-2.5_Sheet1[4B], EVU-BA-2.5_Sheet4[8B]), PC7 (bidir, see EVU-BA-2.5_Sheet1[4B], EVU-BA-2.5_Sheet4[8B]), PC8 (bidir, see EVU-BA-2.5_Sheet1[4B], EVU-BA-2.5_Sheet4[8B]), PC9 (bidir, see EVU-BA-2.5_Sheet1[4B], EVU-BA-2.5_Sheet4[8B]), PC10 (bidir, see EVU-BA-2.5_Sheet1[4B], EVU-BA-2.5_Sheet4[8B]), PC11 (bidir, see EVU-BA-2.5_Sheet1[4B], EVU-BA-2.5_Sheet4[8B]), PC12 (bidir, see EVU-BA-2.5_Sheet1[4B], EVU-BA-2.5_Sheet4[8B]), PC13 (bidir, see EVU-BA-2.5_Sheet1[4B], EVU-BA-2.5_Sheet4[8B]), PC14 (bidir, see EVU-BA-2.5_Sheet1[4B], EVU-BA-2.5_Sheet4[8B]), PC15 (bidir, see EVU-BA-2.5_Sheet1[4B], EVU-BA-2.5_Sheet4[8B]), QSPI1_CS/PB0 (out, see EVU-BA-2.5_Sheet1[4C], EVU-BA-2.5_Sheet4[8C]), QSPI1_IO2/PB4 (bidir, see EVU-BA-2.5_Sheet1[4C], EVU-BA-2.5_Sheet4[8C]), QSPI1_IO3/PB5 (bidir, see EVU-BA-2.5_Sheet1[4C], EVU-BA-2.5_Sheet4[8C]), QSPI1_MISO/PB3 (bidir, see EVU-BA-2.5_Sheet1[4C], EVU-BA-2.5_Sheet4[8C]), QSPI1_MOSI/PB2 (bidir, see EVU-BA-2.5_Sheet1[4C], EVU-BA-2.5_Sheet4[8C]), QSPI1_SCK/PB1 (out, see EVU-BA-2.5_Sheet1[4C], EVU-BA-2.5_Sheet4[8C]), RX_3/PB7 (in, see EVU-BA-2.5_Sheet1[4B], EVU-BA-2.5_Sheet4[8C]), SCK_1/PA9 (in, see EVU-BA-2.5_Sheet1[4C], EVU-BA-2.5_Sheet4[8D]), SCL_0/PA4 (out, see EVU-BA-2.5_Sheet1[4D], EVU-BA-2.5_Sheet3[1B], EVU-BA-2.5_Sheet4[8D]), SDA_0/PA5 (bidir, see EVU-BA-2.5_Sheet1[4D], EVU-BA-2.5_Sheet4[8D]), TCK/PA0 (in, see EVU-BA-2.5_Sheet1[5C], EVU-BA-2.5_Sheet3[1C], EVU-BA-2.5_Sheet4[8D]), TDI/PA3 (in, see EVU-BA-2.5_Sheet1[5C], EVU-BA-2.5_Sheet3[1C], EVU-BA-2.5_Sheet4[8D]), TDO/PA2 (out, see EVU-BA-2.5_Sheet1[5C], EVU-BA-2.5_Sheet3[1C], EVU-BA-2.5_Sheet4[8D]), TIM0_PWM0/PA12 (bidir, see EVU-BA-2.5_Sheet1[4C], EVU-BA-2.5_Sheet4[8D]), TIM1_PWM0/PB12 (bidir, see EVU-BA-2.5_Sheet1[4B], EVU-BA-2.5_Sheet4[8C]), TIM1_PWM1/PB13 (bidir, see EVU-BA-2.5_Sheet1[4B], EVU-BA-2.5_Sheet4[8C]), TIM1_PWM3/PB15 (bidir, see EVU-BA-2.5_Sheet1[4B], EVU-BA-2.5_Sheet4[8C]), TMS/PA1 (in, see EVU-BA-2.5_Sheet1[5C], EVU-BA-2.5_Sheet3[1B], EVU-BA-2.5_Sheet4[8D]), TUSB_INT/PB11 (bidir, see EVU-BA-2.5_Sheet1[4B], EVU-BA-2.5_Sheet4[8C]), TX_3/PB6 (out, see EVU-BA-2.5_Sheet1[4C], EVU-BA-2.5_Sheet4[8C]), UART0_RX/PA7 (in, see EVU-BA-2.5_Sheet1[5D], EVU-BA-2.5_Sheet3[1C], EVU-BA-2.5_Sheet4[8D]), UART0_TX/PA6 (out, see EVU-BA-2.5_Sheet1[5D], EVU-BA-2.5_Sheet3[1C], EVU-BA-2.5_Sheet4[8D]), USER_LED/PC0 (bidir, see EVU-BA-2.5_Sheet1[4B], EVU-BA-2.5_Sheet4[8C]), VBUS_MK_USB (see EVU-BA-2.5_Sheet1[5A], EVU-BA-2.5_Sheet5[8D]), VIN<0> (in, see EVU-BA-2.5_Sheet1[4C], EVU-BA-2.5_Sheet4[8D]), VIN<1> (in, see EVU-BA-2.5_Sheet1[4C], EVU-BA-2.5_Sheet4[8D]), VIN<2> (in, see EVU-BA-2.5_Sheet1[4C], EVU-BA-2.5_Sheet4[8D]), VIN<3> (in, see EVU-BA-2.5_Sheet1[4C], EVU-BA-2.5_Sheet4[8D]), VIN<4> (in, see EVU-BA-2.5_Sheet1[4C], EVU-BA-2.5_Sheet4[8D]), VIN<5> (in, see EVU-BA-2.5_Sheet1[4C], EVU-BA-2.5_Sheet4[8D]), VIN<6> (in, see EVU-BA-2.5_Sheet1[4C], EVU-BA-2.5_Sheet4[8D]), VIN<7> (in, see EVU-BA-2.5_Sheet1[4C], EVU-BA-2.5_Sheet4[8D])

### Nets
3V3: C7.1 C10.1 C23.2 C25.2 C29.2 DD3.12(VDD) DD5.36(V3P3) DD6.3(IN) G1.4(VDD) L3.1 L4.1 L5.1 L6.1 R2.1 R4.1 R6.1 R14.2 R17.1 R23.1 R29.2 R31.2 R32.2 R35.1 R38.2 R39.1 R40.1 R52.1 R111.1 VT1.2(S) XP1.2 XP1.4 XP1.6 XP1.8 XP1.10
5V: C2.1 C11.1 C13.2 DD2.1(VIN) DD4.5(IN)
GND: C2.2 C3.2 C4.2 C5.1 C6.2 C7.2 C8.1 C9.2 C10.2 C11.2 C12.1 C13.1 C14.2 C15.2 C16.1 C17.2 C18.2 C19.2 C20.2 C21.2 C22.2 C23.1 C24.2 C25.1 C26.1 C29.1 C30.2 C31.2 C32.1 C33.1 C34.1 C35.1 C36.1 C37.1 C38.2 C40.2 DD1.4(VSS) DD2.2(GND) DD3.10(GND) DD3.11(EN_N) DD4.2(GND) DD5.89(E-PAD) DD6.1(PGND) DD6.2(GND) DD14.2(GND) G1.2(GND) L7.1 L9.1 R1.1 R13.1 R15.1 R18.2 R19.2 R20.2 R21.2 R30.2 R41.1 R42.2 R54.1 R112.1 R113.2 SB1.3 SB1.4 VT2.2(S) XS1.A1_B12(GND) XS1.B1_A12(GND) XS1.S1(SHIELD) XS1.S2(SHIELD) XS1.S3(SHIELD) XS1.S4(SHIELD)
1V7: C31.1 C37.2 DD5.37(V1P7_LDO) DD5.48(VDD_eFLASH)
3V3_QSPI: C6.1 DD1.8(VCC) R24.2 XP2.2
AREF: R46.2 ; port AREF
CLK_25MHz: DD5.14(CLKI) G1.3(OUT)
CLK_STRAP: R108.2 R113.1 XP1.1
CS_1/PA8: DD5.51(PA[8]) ; port CS_1/PA8
DBG_SEL: R12.2 R19.1 XP1.3
I2C2_SCL/PB8: DD5.3(PB[8]) R33.2 ; port I2C2_SCL/PB8
I2C2_SDA/PB9: DD5.2(PB[9]) R28.2 ; port I2C2_SDA/PB9
ID: DD3.9(ID) R37.1 R44.2
ID_MCU: DD5.15(ID) R37.2 R40.2 R41.2 R114.2
LDO_OUT_1P1: C26.2 C30.1 C33.2 C34.2 C35.2 C36.2 DD5.13(V1P2) DD5.34(V1P2_LDO) DD5.40(V1P2) DD5.55(V1P2) DD5.77(V1P2) L2.1 L8.1
M0: R11.1 R18.1 XP1.9 ; port M0
M1: R10.1 R21.1 XP1.7 ; port M1
M2: R9.2 R20.1 XP1.5 ; port M2
MISO_1/PA11: DD5.45(PA[11]) ; port MISO_1/PA11
MK_N: DD14.3(I/O2) XS1.A7(DN1) XS1.B7(DN2)
MK_P: DD14.1(I/O1) XS1.A6(DP1) XS1.B6(DP2)
MK_USB_N: DD5.20(DM) DD14.4(I/O2)
MK_USB_P: DD5.19(DP) DD14.6(I/O1)
MOSI_1/PA10: DD5.46(PA[10]_¦_MODE[0]) R11.2 ; port MOSI_1/PA10
nRST_MCU: R8.1 R116.1 ; port nRST_MCU
nVBUS_FLG_USB/PB14: DD5.84(PB[14]) R36.2 ; port nVBUS_FLG_USB/PB14
PA13: DD5.42(PA[13]) R114.1 ; port PA13
PA14: DD5.41(PA[14]) ; port PA14
PA15: DD5.39(PA[15]) ; port PA15
PB0: DD5.12(PB[0]) R53.1
PB1: DD5.11(PB[1]) R47.1
PB2: DD5.9(PB[2]) R48.1
PB3: DD5.8(PB[3]) R49.1
PB4: DD5.7(PB[4]) R50.1
PB5: DD5.6(PB[5]) R51.1
PB10: DD5.88(MODE[1]_¦_PB[10]) R10.2 ; port PB10
PC1: DD5.80(PC[1]) ; port PC1
PC2: DD5.79(PC[2]) ; port PC2
PC3: DD5.78(PC[3]) ; port PC3
PC4: DD5.75(MODE[2]_¦_PC[4]) R9.1 ; port PC4
PC5: DD5.74(PC[5]) ; port PC5
PC6: DD5.73(CLK_STRAP_¦_PC[6]) R108.1 ; port PC6
PC7: DD5.72(PC[7]) ; port PC7
PC8: DD5.70(DBG_SEL_¦_PC[8]) R12.1 ; port PC8
PC9: DD5.69(PC[9]) ; port PC9
PC10: DD5.68(PC[10]) ; port PC10
PC11: DD5.67(PC[11]) ; port PC11
PC12: DD5.65(PC[12]) ; port PC12
PC13: DD5.64(PC[13]) R22.2 ; port PC13
PC14: DD5.63(PC[14]) ; port PC14
PC15: DD5.62(PC[15]) R43.2 ; port PC15
QSPI1_CS/PB0: R5.2 R53.2 ; port QSPI1_CS/PB0
QSPI1_IO2/PB4: R3.2 R50.2 ; port QSPI1_IO2/PB4
QSPI1_IO3/PB5: R25.1 R51.2 ; port QSPI1_IO3/PB5
QSPI1_MISO/PB3: R7.2 R49.2 ; port QSPI1_MISO/PB3
QSPI1_MOSI/PB2: R27.1 R48.2 ; port QSPI1_MOSI/PB2
QSPI1_SCK/PB1: R26.1 R47.2 ; port QSPI1_SCK/PB1
RX_3/PB7: DD5.4(PB[7]) ; port RX_3/PB7
SCK_1/PA9: DD5.50(PA[9]) ; port SCK_1/PA9
SCL_0/PA4: DD5.57(PA[4]¦NTRST) ; port SCL_0/PA4
SDA_0/PA5: DD5.56(PA[5]) ; port SDA_0/PA5
TCK/PA0: DD5.61(PA[0]¦TCK) ; port TCK/PA0
TDI/PA3: DD5.58(PA[3]¦TDI) ; port TDI/PA3
TDO/PA2: DD5.59(PA[2]¦TDO) ; port TDO/PA2
TIM0_PWM0/PA12: DD5.43(PA[12]) VT2.3(D) ; port TIM0_PWM0/PA12
TIM1_PWM0/PB12: DD5.86(PB[12]) ; port TIM1_PWM0/PB12
TIM1_PWM1/PB13: DD5.85(PB[13]) ; port TIM1_PWM1/PB13
TIM1_PWM3/PB15: DD5.83(PB[15]) ; port TIM1_PWM3/PB15
TMS/PA1: DD5.60(PA[1]¦TMS) ; port TMS/PA1
TST: DD5.38(TST) R103.1
TUSB_INT/PB11: DD5.87(PB[11]) R34.2 R39.2 ; port TUSB_INT/PB11
TX_3/PB6: DD5.5(PB[6]) ; port TX_3/PB6
UART0_RX/PA7: DD5.52(PA[7]) ; port UART0_RX/PA7
UART0_TX/PA6: DD5.53(PA[6]) ; port UART0_TX/PA6
USER_BUT: R14.1 R22.1 SB1.2
USER_LED/PC0: DD5.81(PC[0]) ; port USER_LED/PC0
VBUS_MK_USB: C8.2 C9.1 DD4.1(OUT) DD14.5(VBUS) L1.2 R16.1 R45.1 ; port VBUS_MK_USB
VCCA: C14.1 DD5.18(VDDIO_USB) L3.2
VDD_PLL: C28.2 DD5.22(VDDA_PLL) L8.2
VDDA: C15.1 DD5.17(V1P2_USB) L2.2
VDDIO: C17.1 C18.1 C19.1 C20.1 C21.1 C22.1 C24.1 DD5.1(VDDIO) DD5.10(VDDIO) DD5.44(VDDIO) DD5.54(VDDIO) DD5.66(VDDIO) DD5.71(VDDIO) DD5.82(VDDIO) L4.2
VIN<0>: DD5.23(VIN0) ; port VIN<0>
VIN<1>: DD5.24(VIN1) ; port VIN<1>
VIN<2>: DD5.25(VIN2) ; port VIN<2>
VIN<3>: DD5.26(VIN3) ; port VIN<3>
VIN<4>: DD5.30(VIN4) ; port VIN<4>
VIN<5>: DD5.31(VIN5) ; port VIN<5>
VIN<6>: DD5.32(VIN6) ; port VIN<6>
VIN<7>: DD5.33(VIN7) ; port VIN<7>
VREF_1V: C32.2 C38.1 DD5.47(VREF_eFLASH) DD6.5(OUT) R52.2 R55.2
VREFN: C27.1 DD5.27(VREFN_ADC) L7.2
VREFP: C27.2 DD5.29(VREFP_ADC) L6.2 R46.1
VSS_PLL: C28.1 DD5.21(VSSA_PLL) L9.2
NetC1_1: C1.1 R1.2
NetC1_2: C1.2 SB1.1
NetC3_1: C3.1 C4.1 C5.2 L1.1 XS1.A4_B9(VBUS) XS1.B4_A9(VBUS)
NetC12_2: C12.2 DD5.28(VDDA_ADC) L5.2
NetC16_2: C16.2 DD5.16(VBUS) R45.2
NetC40_1: C40.1 R111.2 VT1.1(G)
NetDD1_1: DD1.1(S#) R4.2 R5.1
NetDD1_2: DD1.2(DQ1) R7.1
NetDD1_3: DD1.3(W#/DQ2) R2.2 R3.1
NetDD1_5: DD1.5(DQ0) R27.2
NetDD1_6: DD1.6(C) R26.2
NetDD1_7: DD1.7(HOLD#/DQ3) R25.2
NetDD2_3: DD2.3(EN) R6.2 R8.2
NetDD2_5: DD2.5(VOUT) R23.2 R24.1 XP2.1
NetDD3_1: DD3.1(CC1) R15.2 XS1.A5(CC1)
NetDD3_2: DD3.2(CC2) R13.2 XS1.B5(CC2)
NetDD3_3: DD3.3(PORT) R17.2 R112.2
NetDD3_4: DD3.4(VBUS_DET) R16.2
NetDD3_5: DD3.5(ADDR) R30.1 R32.1
NetDD3_6: DD3.6(INT_N/OUT3) R34.1
NetDD3_7: DD3.7(SDA/OUT1) R28.1 R31.1
NetDD3_8: DD3.8(SCL/OUT2) R29.1 R33.1
NetDD4_3: DD4.3(FLG) R36.1 R38.1
NetDD4_4: DD4.4(EN) R42.1 R43.1 R44.1
NetDD5_49: DD5.49(NRESET) R116.2
NetDD5_76: DD5.76(POR_OK) X1.1(X)
NetDD6_4: DD6.4(FB) R54.2 R55.1
NetG1_1: G1.1(TRI-STATE) R35.2
NetR103_2: R103.2 VT1.3(D) VT2.1(G)

Not connected (* = marked no-connect by the designer): DD2 4(NC); DD5 35(NC); XS1 A8(SBU1) B8(SBU2)

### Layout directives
differential pair: MK_N, MK_P, MK_USB_N, MK_USB_P

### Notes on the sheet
- (near XP1) DBG
- (near XP1) CLK
- (near DD5) JTAG
- (near DD5) I2C2_SCL
- (near DD5) I2C2_SDA
- 0 – external source CLKI
  1 – internal RC generator
- (near XP1) M1
- (near XP1) M2
- (near DD5) UART0_TX
- (near DD5) UART0_RX
- (near XP1) M0
- (near DD5) SPI1
- (near C3) STRAP CONFIG
  CLK
  DBG, M2, M1, M0
- 0000 – EFLASH
  0001 – UART
  0010 – QSPI
  0011 – USB
  0100 – JTAG EXT
  0101 – PYTH UART
  0110 – MULTI
  0111 – FACT RST
  1001 - USB/UART
  1100 - JTAG INT
  1101 - PYTH USB
- POWER Switch
- (near DD5) TCK
- (near DD5) TMS
- (near XS1) MCU USB
- (near DD5) USB
- (near DD5) TDO
- (near DD5) TDI
- (near DD5) TRST
- (near DD5) ADC
- (near DD3) USB_OTG
- (near DD5) Baikal MCU
- USER BUTTON
- (near R111) Workaround sch
- Voltage
  References 1V
- Serial SPI NOR Flash

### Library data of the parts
C1 C3 C7 C9-C12 C14-C26 C29 C32-C37 = C0603C104K5RAC: as C39 on sheet EVU-BA-2.5_Sheet3
C2 C5 C6 C8 C27 C28 C30 C31 C40 = GRM188R71C105KA12D: 0603 X7R 1,0 uF±10% 16V; Manufacturer: "Murata"; Tolerance: ±10%; NOM: 0603 X7R 1uF ±10% 16V; Value Ru: 1,0 мкФ
C4 = 293D106X0020B2TE3: 10 uF±20% 20V, Tantal capacitor, Type B; Manufacturer: "Vishay"; Tolerance: ±20%; NOM: Type B 10uF ±20% 20V; TKE: Type B; Value Ru: 10мкФ
C13 = GRM31CR71E106KA12L: 1206 X7R 10 uF±10% 25V; Manufacturer: "Murata"; Tolerance: ±10%; Value Ru: 10 мкФ
C38 = GRM188R71E474KA12D: 0603 X7R 470 nF±10% 25V; Manufacturer: "Murata"; Tolerance: ±10%; Value Ru: 0,47 мкФ
DD1 = MT25QL128ABA1ESE: NOR Flash Serial (SPI, Dual SPI, Quad SPI) 3V/3.3V 128M-bit 128M; Manufacturer_Part_Number: MT25QL128ABA1ESE-0SIT TR; Manufacturer: "Micron"
DD2 = AP2112K-3.3TRG1: LDO voltage regulator Vout -3.3V, Iout - 0.6A max, Vout accuracy ±1.5%; Manufacturer_Name: Diodes Incorporated; Manufacturer: "Diodes"
DD3 = TUSB320RWBR: USB Type-C Logic & Port Control; Manufacturer: "Texas Instruments"
DD4 = AP2191WG-7: Power switch, USB switch, 1.5A; Manufacturer: "Diodes Incorporated"
DD5 = BE-U1000: Microcontroller BE-U1000; Manufacturer: "Baikal Electronics"; TKE: QFN 88
DD6 = ZXRE160H5TA: V-Ref Adjustable 0.2V to 18V 15mA; Manufacturer: "Diodes Incorporated"; TKE: SOT-353
DD14 = USBLC6-2SC6: as DD15 on sheet EVU-BA-2.5_Sheet3
G1 = OT322525MJBA4SL: 3.3V ±10ppm 5mA ±20ppm CMOS 25MHz  Oscillator; Manufacturer: "YXC"; TKE: SMD3225-4P
L1 = BLM18SG331TN1: as L10 on sheet EVU-BA-2.5_Sheet3
L2-L9 = BLM18PG471SN1: as L11 on sheet EVU-BA-2.5_Sheet3
R1 = CR0603-JW-101-E: 0603 100 Ohm±5% 0,1W; Manufacturer: "Bourns"; TKE: 0603; MARK: 101; Power_Voltage: 0,1W; NOM: 0603 100R ±5% 0,1W; Tolerance: ±5%; Value Ru: 100 Ом
R2 R4 R6 R9-R12 R14 R17 R30 R32 R35 R38 R108 R112 = CR0603-JW-103-E: as R59 on sheet EVU-BA-2.5_Sheet3
R3 R5 R7 R25-R27 = CR0603-JW-220-E: as R72 on sheet EVU-BA-2.5_Sheet3
R8 R22-R24 R34 R36 R37 R43 R44 R46-R51 R53 R114 R116 = CR0603-J/-000-E: as R56 on sheet EVU-BA-2.5_Sheet3
R13 R15 = CR0603-JW-512-E: as R109 on sheet EVU-BA-2.5_Sheet3
R16 = CR0603-FX-8873-E: 0603 887 kOhm ±1% 0,1W; Manufacturer: "Bourns"; TKE: 0603; MARK: 92D; Power_Voltage: 0,1 Вт; NOM: 0603 887K ±1% 0,1 Вт; Value Ru: 887 кОм
R18-R21 R42 R111 R113 = CR0603-JW-104-E: 0603 100 kOhm±5% 0.1W; Manufacturer: "Bourns"; TKE: 0603; MARK: 104; Power_Voltage: 0,1 Вт; NOM: 0603 100K ±5% 0,1 Вт; Tolerance: ±5%; Value Ru: 100 кОм
R28 R33 = CR0603-JW-220-E: 0603 22 Ohm ±5% 0.1W; Manufacturer: "Bourns"; TKE: 0603; MARK: 220; Power_Voltage: 0,1 Вт; NOM: 0603 22R ±5% 0,1 Вт; Value Ru: 22 Ом
R29 R31 = CR0603-JW-472-E: 0603 4,7 kOhm±5% 0.1W; Manufacturer: "Bourns"; TKE: 0603; MARK: 472; Power_Voltage: 0,1 Вт; NOM: 0603 4K7 ±5% 0,1 Вт; Tolerance: ±5%; Value Ru: 4,7 кОм
R39-R41 = CR0603-JW-204-E: 0603 200 kOhm±5% 0.1W; Manufacturer: "Bourns"; TKE: 0603; MARK: 204; Power_Voltage: 0,1 Вт; NOM: 0603 200K ±5% 0,1 Вт; Tolerance: ±5%; Value Ru: 200 кОм
R45 R103 = CR0603-JW-102-E: as R117 on sheet EVU-BA-2.5_Sheet3
R52 = CR0603-JW-102-E: 0603 1 kOhm±5% 0,1W; Manufacturer: "Bourns"; TKE: 0603; MARK: 102; Power_Voltage: 0,1 Вт; Tolerance: ±5%; NOM: 0603 1 кОм ±5% 0,1 Вт; Value: 1 кОм
R54 = CR0603-FX-1502-E: 0603 15 kOhm ±1% 0,1W; Manufacturer: "Bourns"; TKE: 0603; MARK: 18C; Power_Voltage: 0,1 Вт; NOM: 0603 15K ±1% 0,1 Вт; Value Ru: 15 кОм
R55 = CR0603-FX-1002-E: 0603 10 kOhm±1% 0,1W; Manufacturer: "Bourns"; TKE: 0603; MARK: 01C; Power_Voltage: 0,1 Вт; NOM: 0603 10K ±1% 0,1 Вт; Value Ru: 10 кОм
SB1 = B3SL-1002P: Surface-mounting Sealed Tactile Switch; ManufacturerPartNumber: B3SL-1022P; Manufacturer: "Omron Corporation"
VT1 = BSS84: P-MOSFET 50V 130mA SOT-23-3; Manufacturer: "NXP Semiconductors"
VT2 = BSS138: N-MOSFET 50V 200mA SOT-23-3; Manufacturer: "Fairchild Semiconductor"
XP1 = DS1021-2x5SF11-B: Connector 2.54 pitch, 2 rows, 8.54 height, 5 pins per row; Manufacturer: "Connfly"
XP2 = DS1021-1x2SF11-B: as XP3 on sheet EVU-BA-2.5_Sheet3
XS1 = TYPE-C-31-M-12: as XS2 on sheet EVU-BA-2.5_Sheet3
